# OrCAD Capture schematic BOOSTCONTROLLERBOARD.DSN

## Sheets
1 1 Microcontroller: size C; title: Boost Controller Board - Microcontroller; note: 10021168
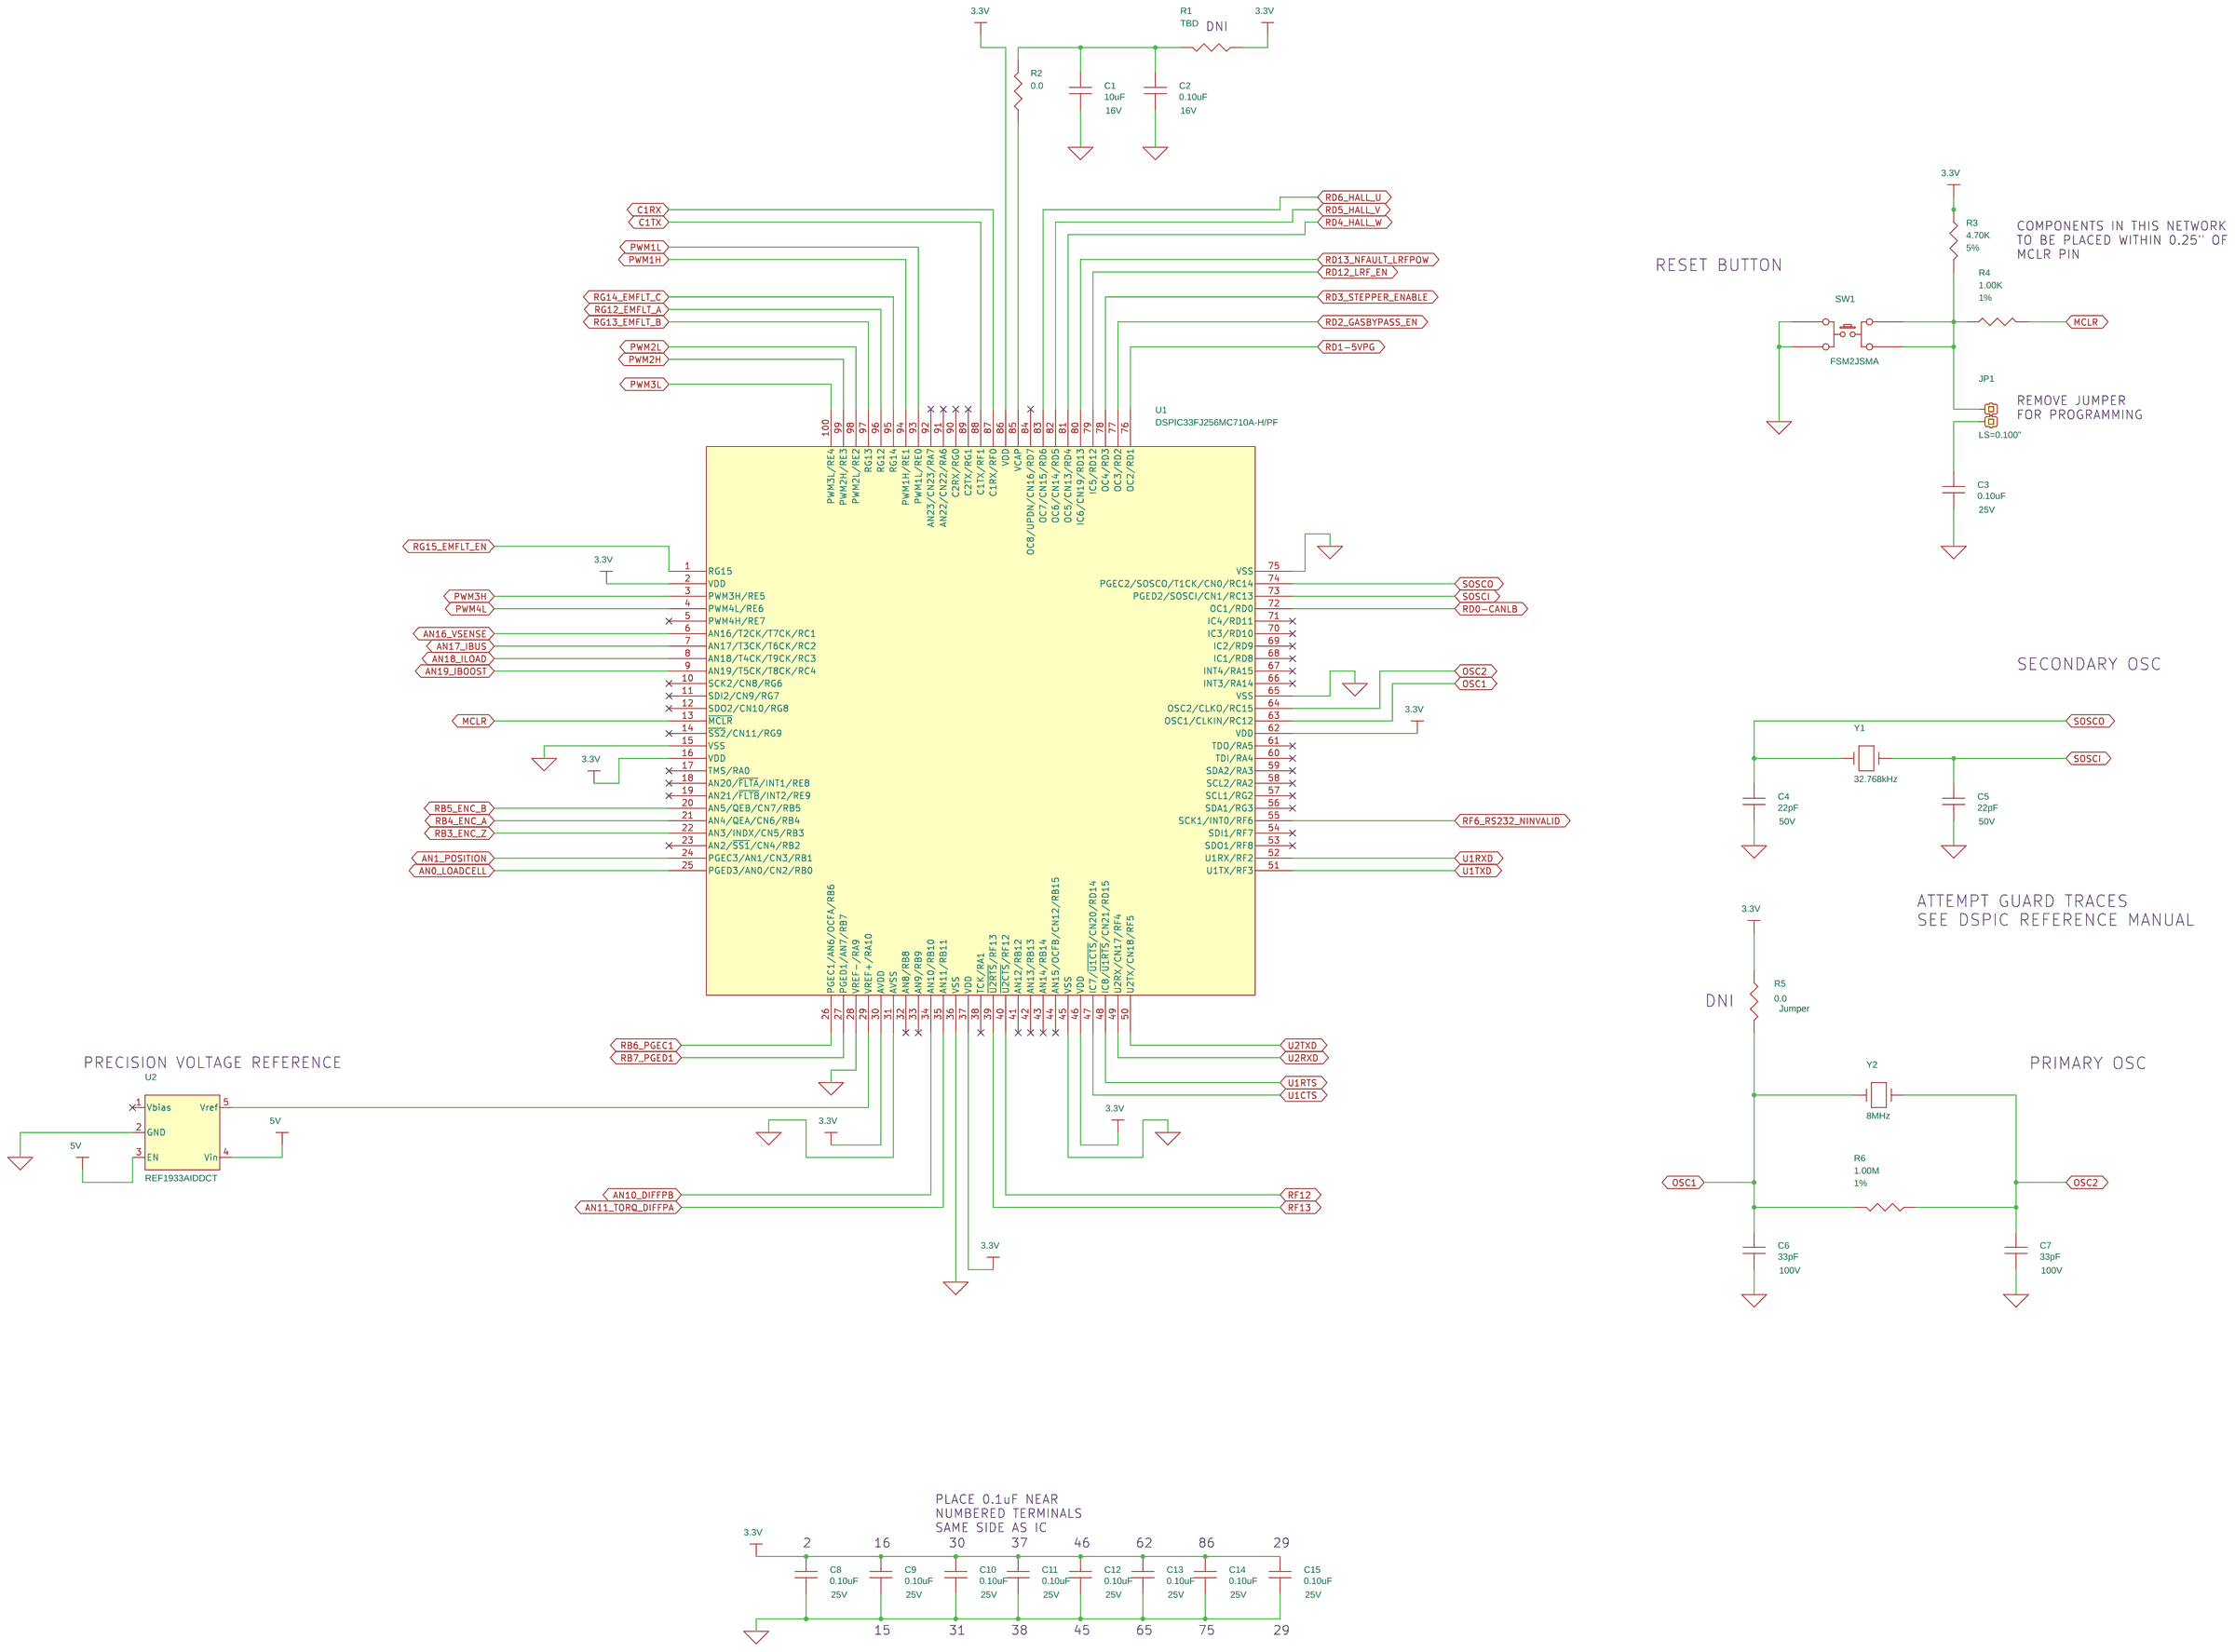
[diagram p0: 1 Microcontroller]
2 2 Power Supply: size C; title: Boost Controller Board - Power Supply
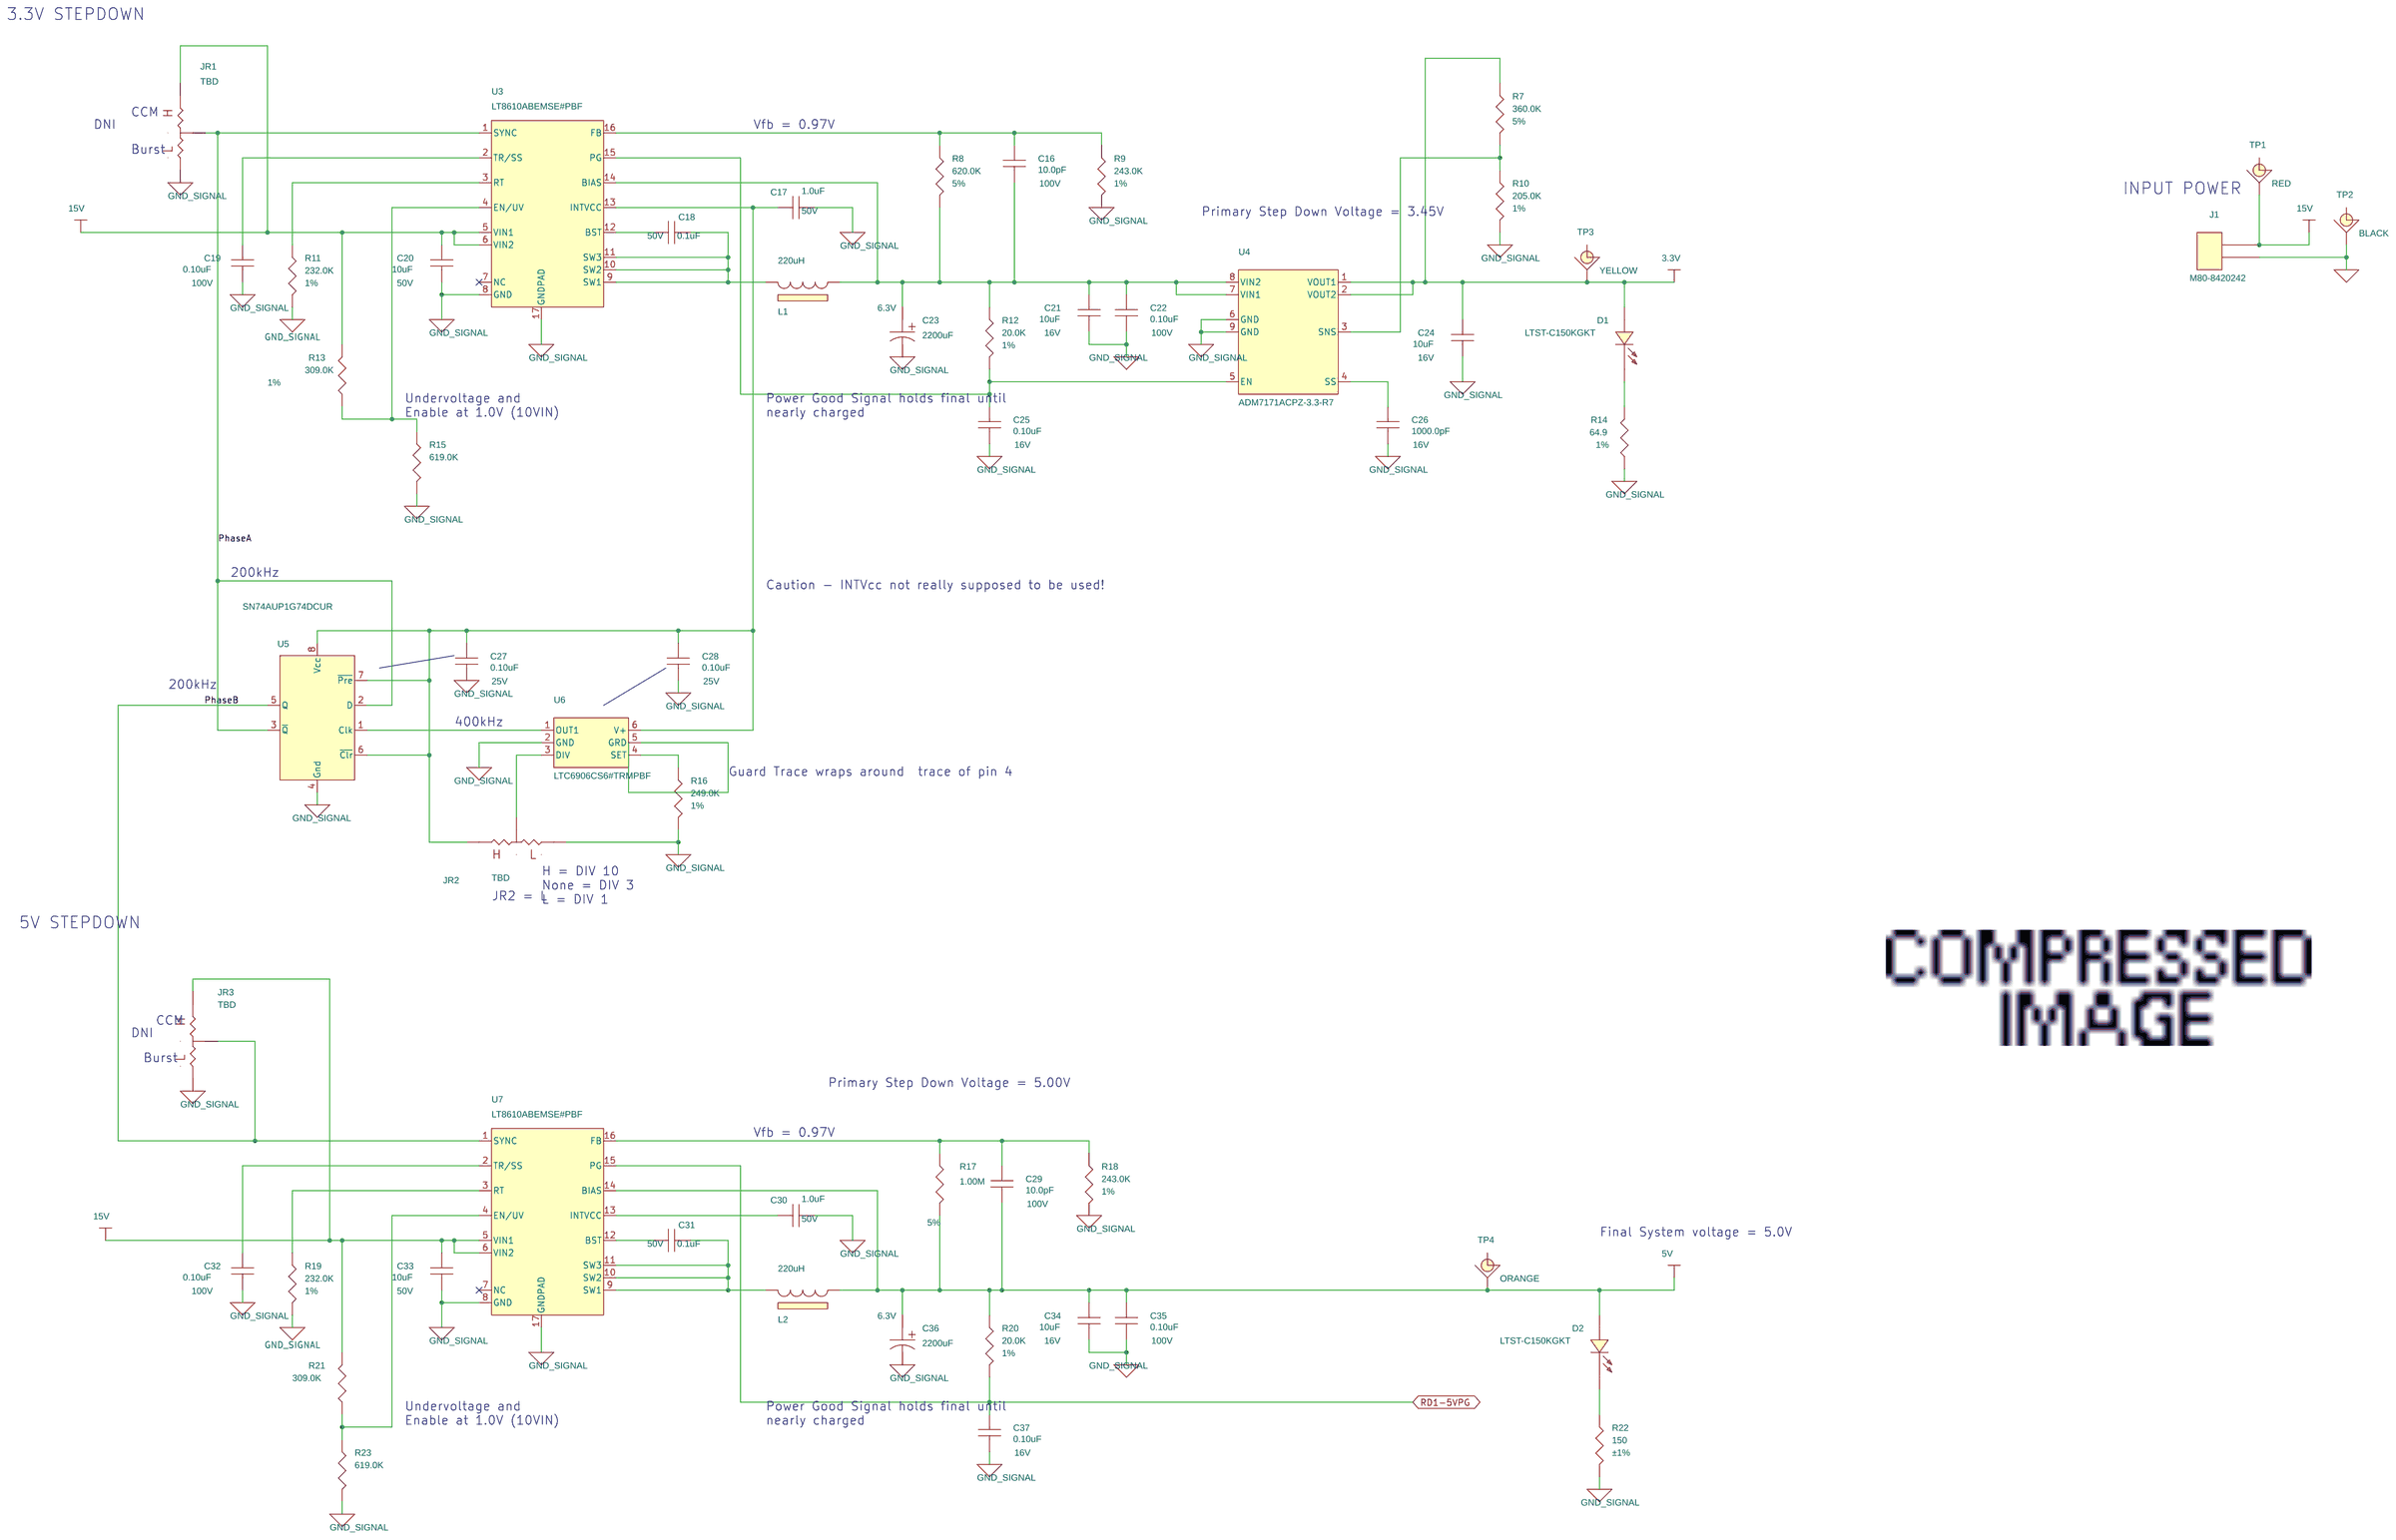
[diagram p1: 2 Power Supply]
3 3 Telemetry: size C; title: Boost Controller Board - Telemetry
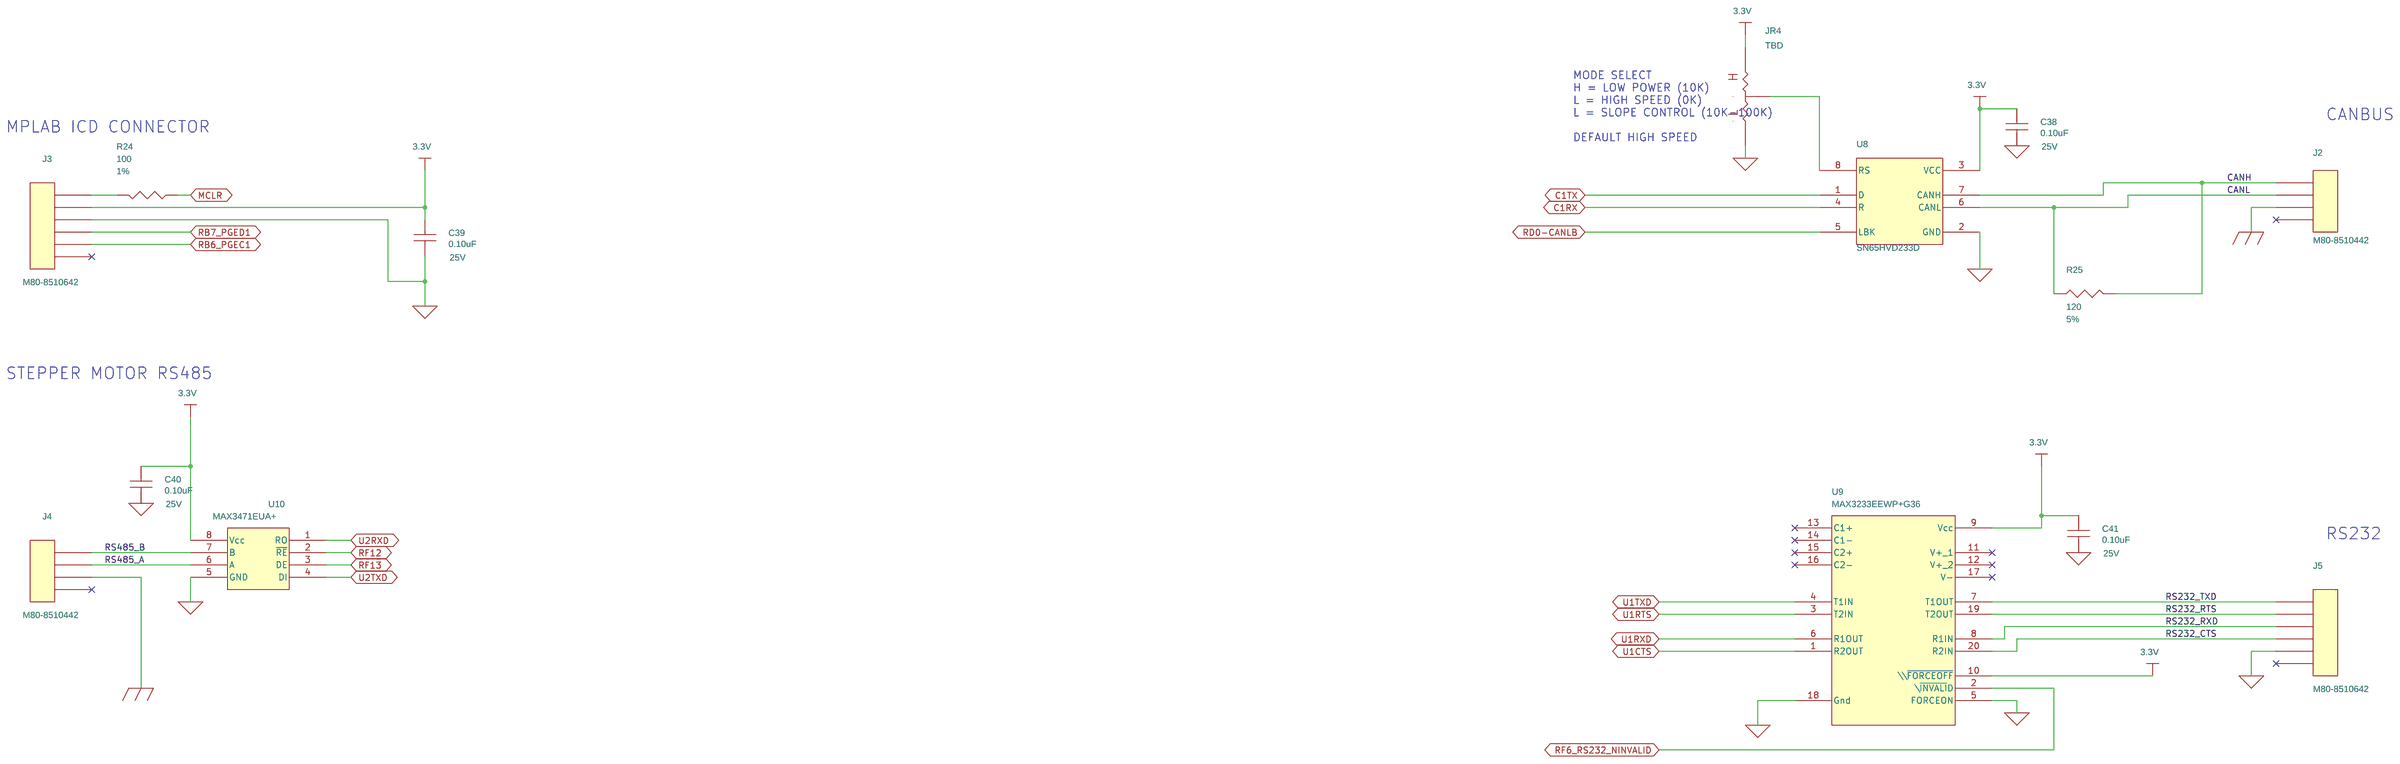
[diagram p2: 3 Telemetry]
4 5 Analog Inputs Sensors: size C; title: Boost Controller Board - Analog Inputs - Sensors
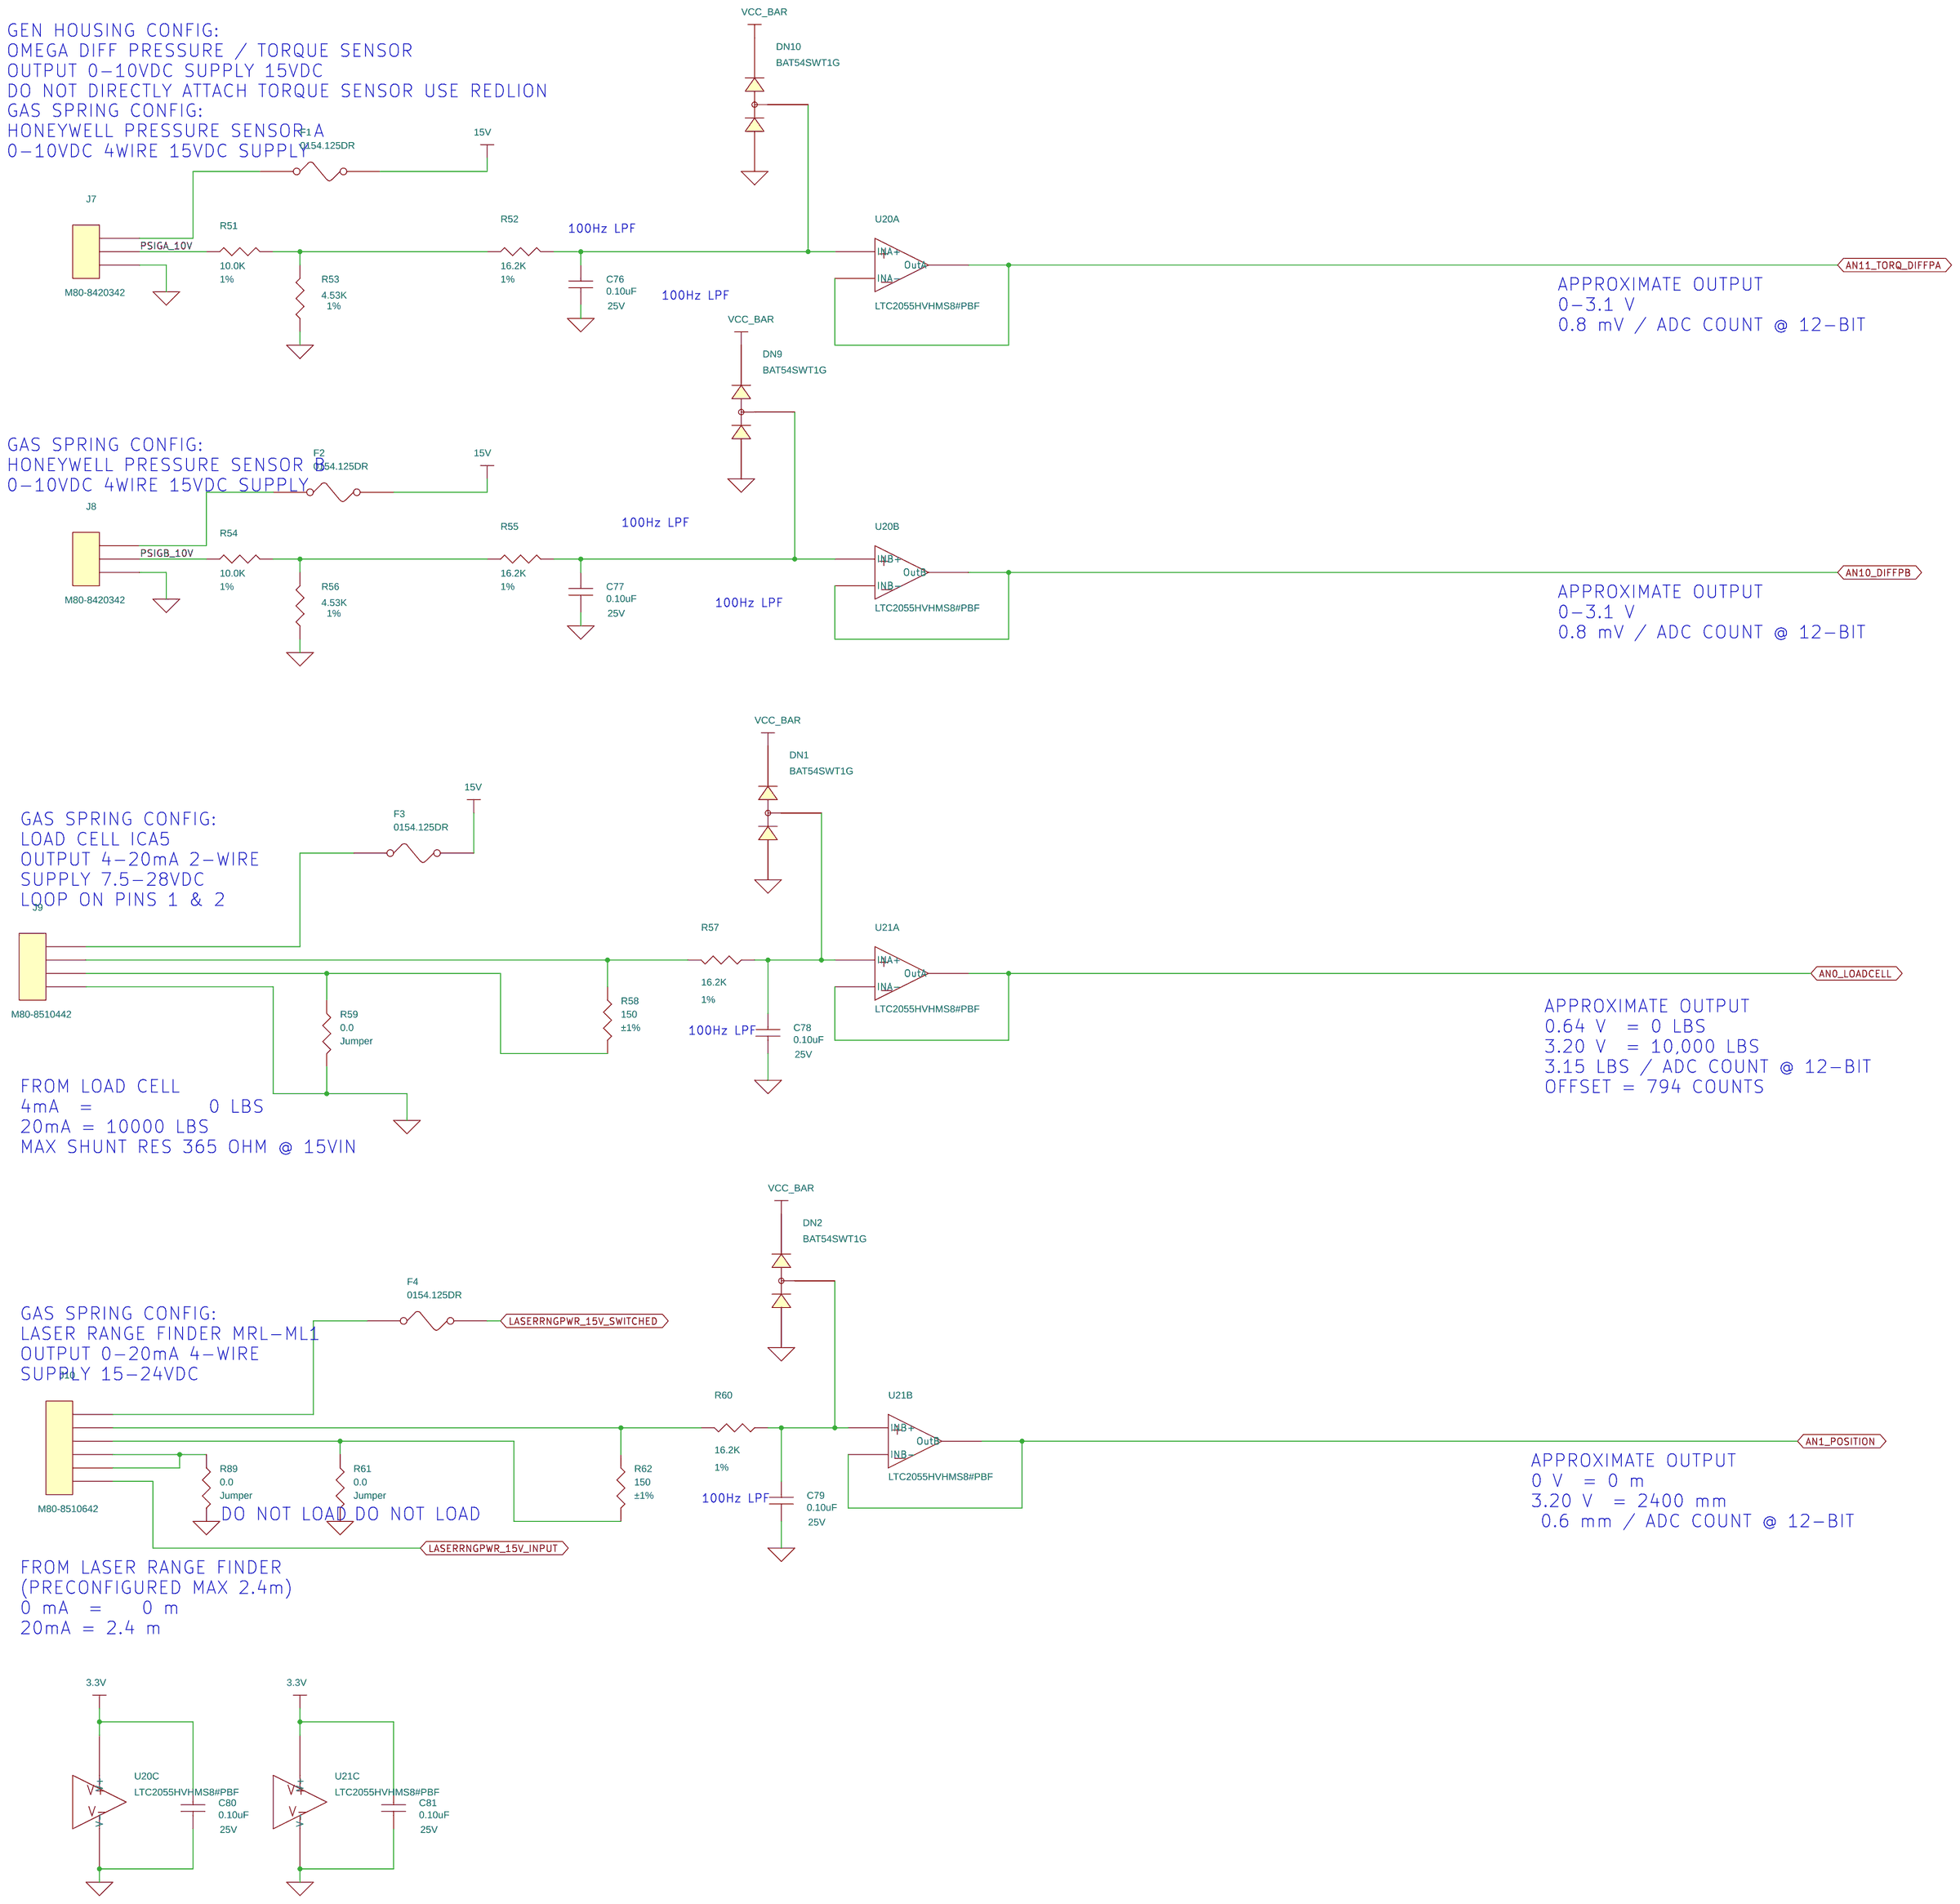
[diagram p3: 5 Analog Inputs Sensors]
5 6 Digital I/O: size C; title: Boost Controller Board - Digital I/O
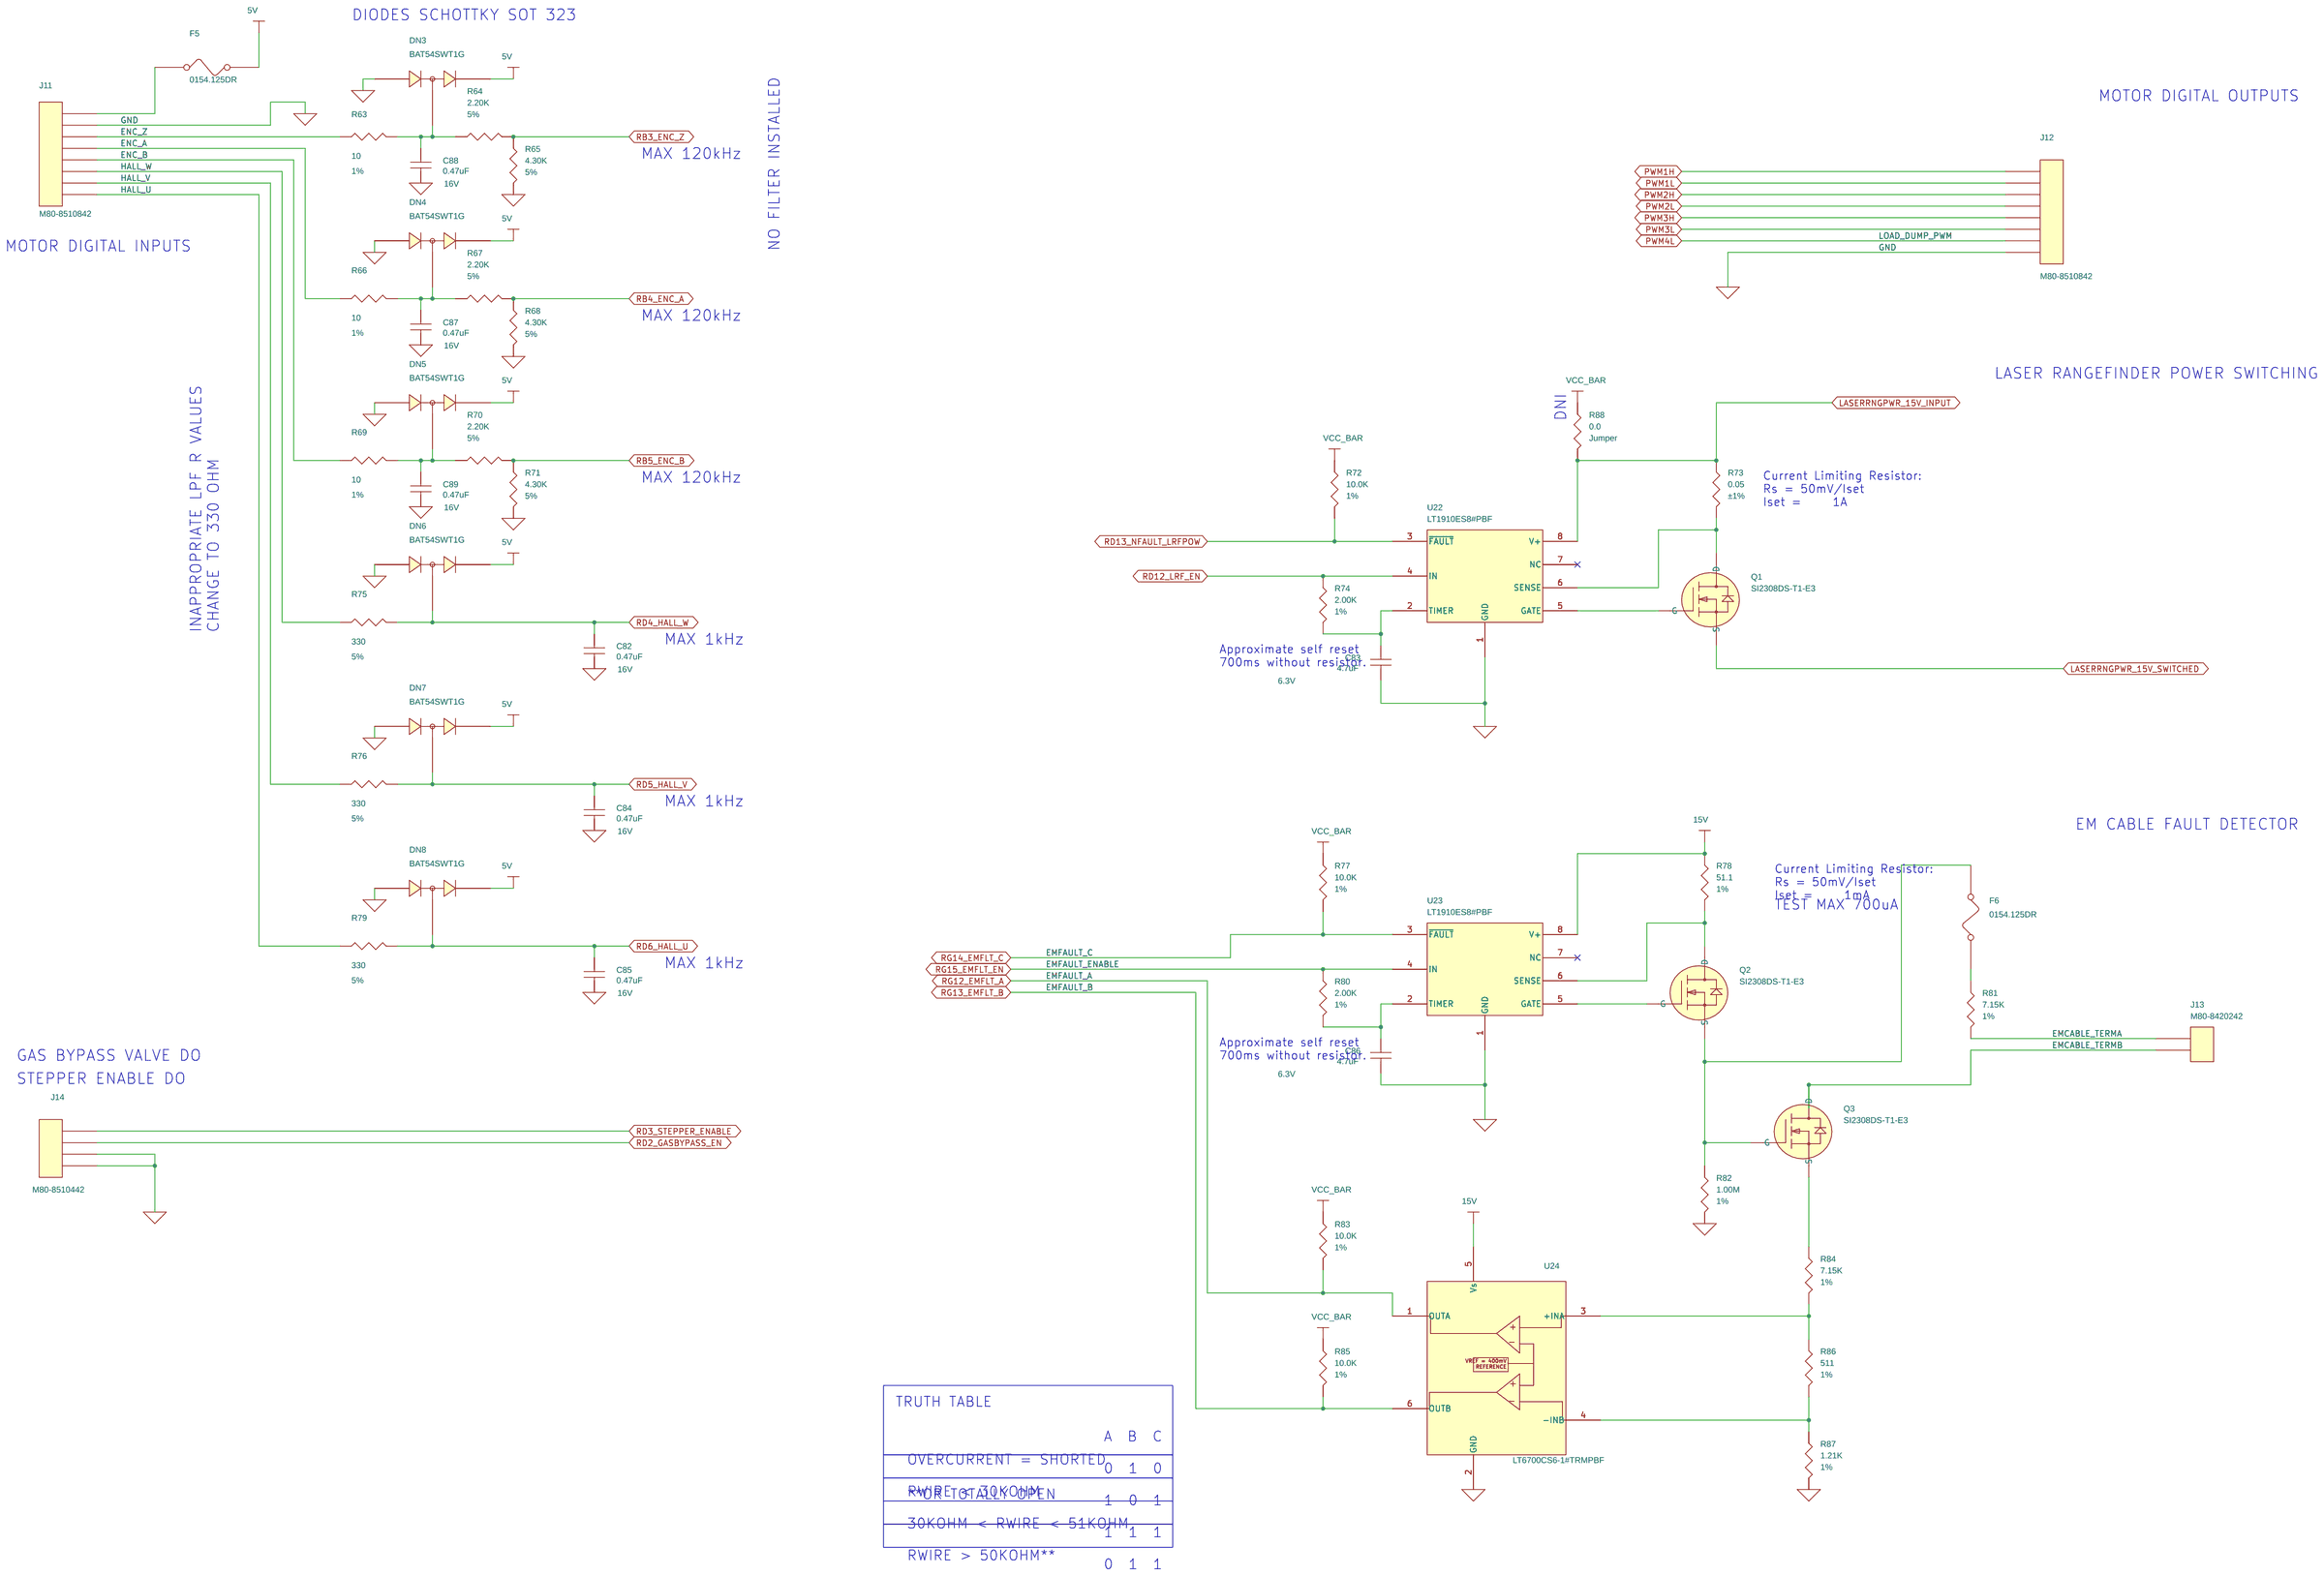
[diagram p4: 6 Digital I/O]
6 4 Analog Inputs V/I Monitors: size C; title: Boost Controller Board - Analog Inputs - Monitors
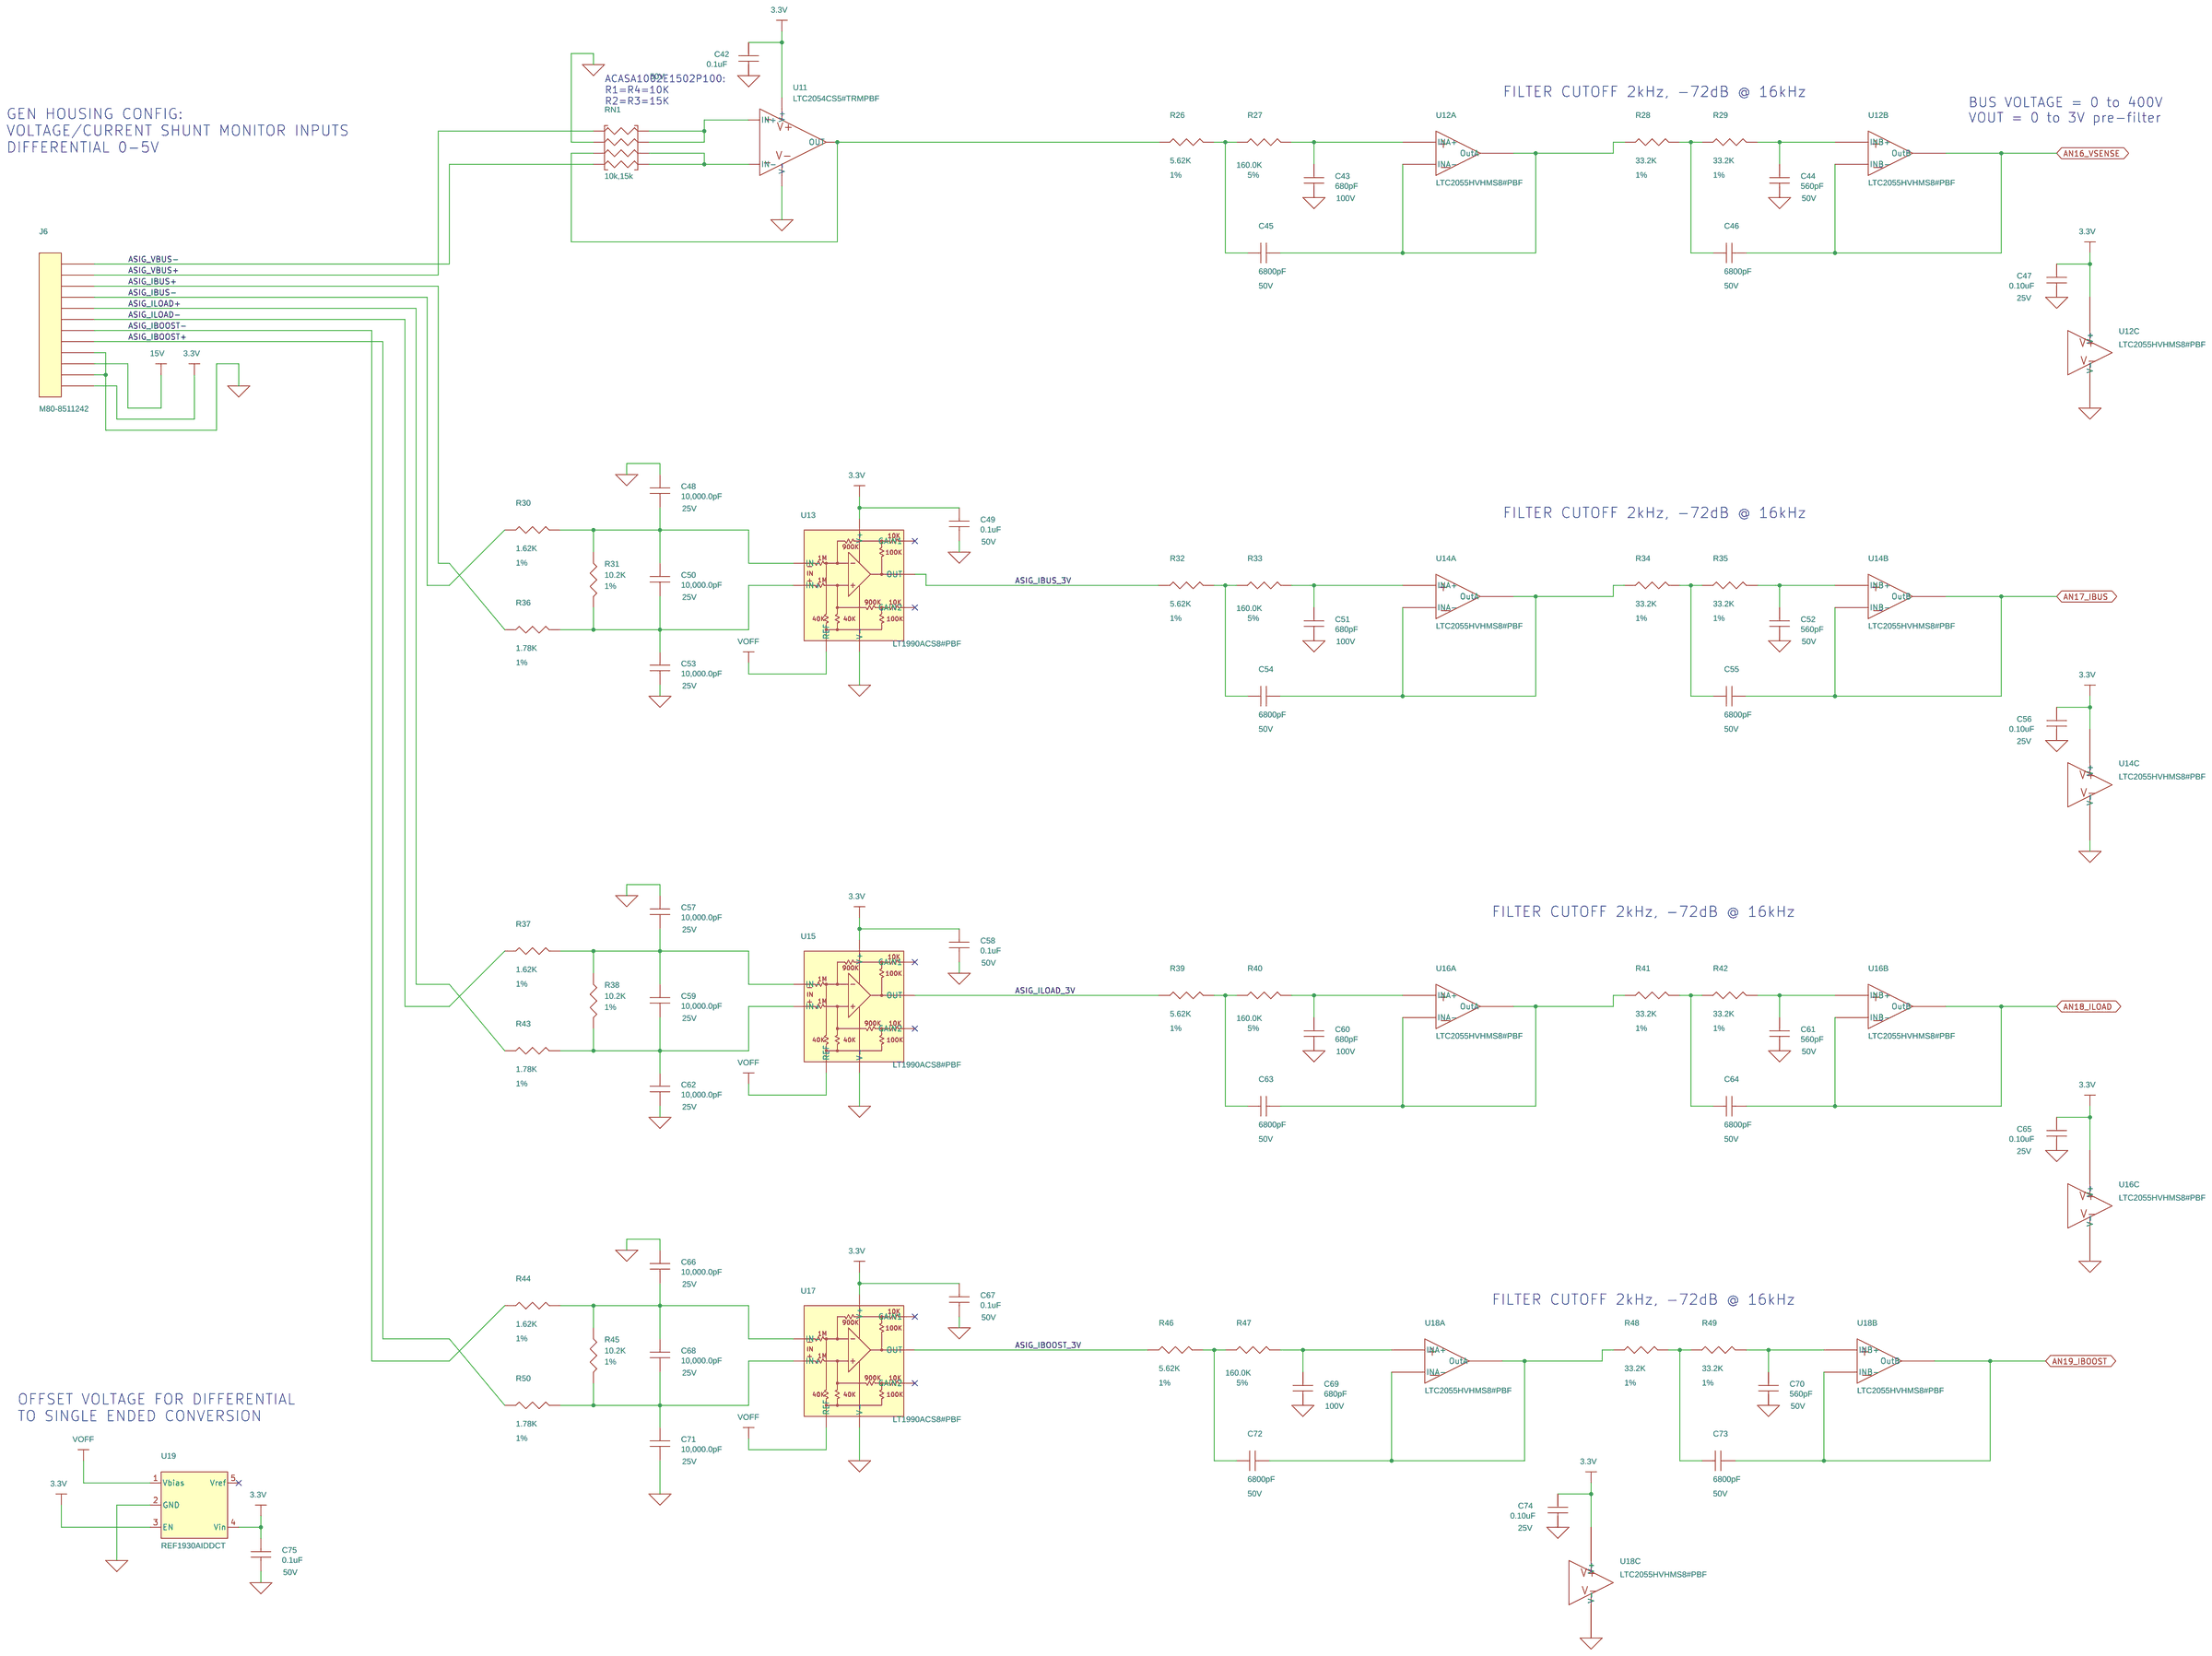
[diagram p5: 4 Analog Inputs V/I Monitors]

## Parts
sheet 1 Microcontroller
C1  10uF  [CAPC2012X135N]
C2  0.10uF  [CAPC1608X87N]
C3  0.10uF  [CAPC1608X87N]
C4  22pF  [CAPC1608X90N_G100]
C5  22pF  [CAPC1608X90N_G100]
C6  33pF  [CAPC1608X90N]
C7  33pF  [CAPC1608X90N]
C8  0.10uF  [CAPC1608X87N]
C9  0.10uF  [CAPC1608X87N]
C10  0.10uF  [CAPC1608X87N]
C11  0.10uF  [CAPC1608X87N]
C12  0.10uF  [CAPC1608X87N]
C13  0.10uF  [CAPC1608X87N]
C14  0.10uF  [CAPC1608X87N]
C15  0.10uF  [CAPC1608X87N]
JP1  LS=0.100"  [HDRV2W64P254_2X1_508X254H1363B]
R1  TBD  [RESC2012X50N]
R2  0.0  [RESC2012X50N]
R3  4.70K  [RESC1608X50N]
R4  1.00K  [RESC1608X50N]
R5  0.0  [RESC1609X55N]
R6  1.00M  [RESC2012X50N]
SW1  FSM2JSMA  [SOIC450P1000X459R-4N]
U1  DSPIC33FJ256MC710A-H/PF  [QFP50P1600X1600X120-100L30N]
U2  REF1933AIDDCT  [SOT95P280X110-5L30N]
Y1  32.768kHz  [OSCCC150X320X90-2N]
Y2  8MHz  [XTALSC500X500X135-2N]
sheet 2 Power Supply
C16  10.0pF  [CAPC2012X88N]
C17  1.0uF  [CAPC2012X140N]
C18  0.1uF  [CAPC2013X94N]
C19  0.10uF  [CAPC2012X110N]
C20  10uF  [CAPC5750X250N]
C21  10uF  [CAPC2012X135N]
C22  0.10uF  [CAPC2012X110N]
C23  2200uF  [CAPAE1030X1380DD450L320N]
C24  10uF  [CAPC2012X135N]
C25  0.10uF  [CAPC2012X100N]
C26  1000.0pF  [CAPC2012X88N]
C27  0.10uF  [CAPC1608X87N]
C28  0.10uF  [CAPC1608X87N]
C29  10.0pF  [CAPC2012X88N]
C30  1.0uF  [CAPC2012X140N]
C31  0.1uF  [CAPC2013X94N]
C32  0.10uF  [CAPC2012X110N]
C33  10uF  [CAPC5750X250N]
C34  10uF  [CAPC2012X135N]
C35  0.10uF  [CAPC2012X110N]
C36  2200uF  [CAPAE1030X1380DD450L320N]
C37  0.10uF  [CAPC2012X100N]
D1  LTST-C150KGKT  [LED_LTST-C150xxx]
D2  LTST-C150KGKT  [LED_LTST-C150xxx]
J1  M80-8420242  [HARWIN_M80-8420242]
JR1  TBD  [MISC_0805-3P-JMPR]
JR2  TBD  [MISC_0805-3P-JMPR]
JR3  TBD  [MISC_0805-3P-JMPR]
L1  220uH  [IND_NS-12]
L2  220uH  [IND_NS-12]
R7  360.0K  [RESC1608X50N]
R8  620.0K  [RESC2012X50N]
R9  243.0K  [RESC2012X50N]
R10  205.0K  [RESC1608X50N]
R11  232.0K  [RESC2012X50N]
R12  20.0K  [RESC2012X50N]
R13  309.0K  [RESC2012X50N]
R14  64.9  [RESC1608X50N]
R15  619.0K  [RESC2012X50N]
R16  249.0K  [RESC2012X50N]
R17  1.00M  [RESC1608X50N]
R18  243.0K  [RESC1608X50N]
R19  232.0K  [RESC2012X50N]
R20  20.0K  [RESC2012X50N]
R21  309.0K  [RESC2012X50N]
R22  150  [RESC1609X55N]
R23  619.0K  [RESC2012X50N]
TP1  RED  [TP_KEYSTONE_5000s_MINI]
TP2  BLACK  [TP_KEYSTONE_5000s_MINI]
TP3  YELLOW  [TP_KEYSTONE_5000s_MINI]
TP4  ORANGE  [TP_KEYSTONE_5000s_MINI]
U3  LT8610ABEMSE#PBF  [SOP50P490X110-17L30T175X364N]
U4  ADM7171ACPZ-3.3-R7  [SON50P300X300X80-9T170X254N]
U5  SN74AUP1G74DCUR  [SOP50P310X90-8N]
U6  LTC6906CS6#TRMPBF  [SOT95P280X100-6L20N]
U7  LT8610ABEMSE#PBF  [SOP50P490X110-17L30T175X364N]
sheet 3 Telemetry
C38  0.10uF  [CAPC1608X87N]
C39  0.10uF  [CAPC1608X87N]
C40  0.10uF  [CAPC1608X87N]
C41  0.10uF  [CAPC1608X87N]
J2  M80-8510442  [HARWIN_M80-8510442]
J3  M80-8510642  [HARWIN_M80-8510642]
J4  M80-8510442  [HARWIN_M80-8510442]
J5  M80-8510642  [HARWIN_M80-8510642]
JR4  TBD  [MISC_0805-3P-JMPR]
R24  100  [RESC2012X50N]
R25  120  [RESC2012X50N]
U8  SN65HVD233D  [SOIC127P600X175-8L87N]
U9  MAX3233EEWP+G36  [SOIC127P1032X265-20N]
U10  MAX3471EUA+  [SOP65P490X110-8L25N]
sheet 4 Analog Inputs V/I Monitors
C42  0.1uF  [CAPC2013X94N]
C43  680pF  [CAPC2012X88N]
C44  560pF  [CAPC1608X90N]
C45  6800pF  [CAPC2012X90N]
C46  6800pF  [CAPC2012X90N]
C47  0.10uF  [CAPC1608X87N]
C48  10,000.0pF  [CAPC2012X88N]
C49  0.1uF  [CAPC2013X94N]
C50  10,000.0pF  [CAPC2012X88N]
C51  680pF  [CAPC2012X88N]
C52  560pF  [CAPC1608X90N]
C53  10,000.0pF  [CAPC2012X88N]
C54  6800pF  [CAPC2012X90N]
C55  6800pF  [CAPC2012X90N]
C56  0.10uF  [CAPC1608X87N]
C57  10,000.0pF  [CAPC2012X88N]
C58  0.1uF  [CAPC2013X94N]
C59  10,000.0pF  [CAPC2012X88N]
C60  680pF  [CAPC2012X88N]
C61  560pF  [CAPC1608X90N]
C62  10,000.0pF  [CAPC2012X88N]
C63  6800pF  [CAPC2012X90N]
C64  6800pF  [CAPC2012X90N]
C65  0.10uF  [CAPC1608X87N]
C66  10,000.0pF  [CAPC2012X88N]
C67  0.1uF  [CAPC2013X94N]
C68  10,000.0pF  [CAPC2012X88N]
C69  680pF  [CAPC2012X88N]
C70  560pF  [CAPC1608X90N]
C71  10,000.0pF  [CAPC2012X88N]
C72  6800pF  [CAPC2012X90N]
C73  6800pF  [CAPC2012X90N]
C74  0.10uF  [CAPC1608X87N]
C75  0.1uF  [CAPC2013X94N]
J6  M80-8511242  [HARWIN_M80-8511242]
R26  5.62K  [RESC2012X50N]
R27  160.0K  [RESC2012X50N]
R28  33.2K  [RESC2012X50N]
R29  33.2K  [RESC2012X50N]
R30  1.62K  [RESC2012X50N]
R31  10.2K  [RESC2012X50N]
R32  5.62K  [RESC2012X50N]
R33  160.0K  [RESC2012X50N]
R34  33.2K  [RESC2012X50N]
R35  33.2K  [RESC2012X50N]
R36  1.78K  [RESC2012X50N]
R37  1.62K  [RESC2012X50N]
R38  10.2K  [RESC2012X50N]
R39  5.62K  [RESC2012X50N]
R40  160.0K  [RESC2012X50N]
R41  33.2K  [RESC2012X50N]
R42  33.2K  [RESC2012X50N]
R43  1.78K  [RESC2012X50N]
R44  1.62K  [RESC2012X50N]
R45  10.2K  [RESC2012X50N]
R46  5.62K  [RESC2012X50N]
R47  160.0K  [RESC2012X50N]
R48  33.2K  [RESC2012X50N]
R49  33.2K  [RESC2012X50N]
R50  1.78K  [RESC2012X50N]
RN1  10k,15k  [RESCAXS80P150X150X55-8N]
U11  LTC2054CS5#TRMPBF  [SOT95P280X100-5N]
U12  LTC2055HVHMS8#PBF  [SOP65P490X110-8L30N]  (sections A,B,C)
U13  LT1990ACS8#PBF  [SOIC127P599X175-8L86N]
U14  LTC2055HVHMS8#PBF  [SOP65P490X110-8L30N]  (sections A,B,C)
U15  LT1990ACS8#PBF  [SOIC127P599X175-8L86N]
U16  LTC2055HVHMS8#PBF  [SOP65P490X110-8L30N]  (sections A,B,C)
U17  LT1990ACS8#PBF  [SOIC127P599X175-8L86N]
U18  LTC2055HVHMS8#PBF  [SOP65P490X110-8L30N]  (sections A,B,C)
U19  REF1930AIDDCT  [SOT95P280X110-5L30N]
sheet 5 Analog Inputs Sensors
C76  0.10uF  [CAPC1608X87N]
C77  0.10uF  [CAPC1608X87N]
C78  0.10uF  [CAPC1608X87N]
C79  0.10uF  [CAPC1608X87N]
C80  0.10uF  [CAPC1608X87N]
C81  0.10uF  [CAPC1608X87N]
DN1  BAT54SWT1G  [SOT65P220X100-3N_132]
DN2  BAT54SWT1G  [SOT65P220X100-3N_132]
DN9  BAT54SWT1G  [SOT65P220X100-3N_132]
DN10  BAT54SWT1G  [SOT65P220X100-3N_132]
F1  0154.125DR  [FUSM9750X381N]
F2  0154.125DR  [FUSM9750X381N]
F3  0154.125DR  [FUSM9750X381N]
F4  0154.125DR  [FUSM9750X381N]
J7  M80-8420342  [HARWIN_M80-8420342]
J8  M80-8420342  [HARWIN_M80-8420342]
J9  M80-8510442  [HARWIN_M80-8510442]
J10  M80-8510642  [HARWIN_M80-8510642]
R51  10.0K  [RESC1608X50N]
R52  16.2K  [RESC1608X50N]
R53  4.53K  [RESC1608X50N]
R54  10.0K  [RESC1608X50N]
R55  16.2K  [RESC1608X50N]
R56  4.53K  [RESC1608X50N]
R57  16.2K  [RESC1608X50N]
R58  150  [RESC6332X70N]
R59  0.0  [RESC2012X50N]
R60  16.2K  [RESC1608X50N]
R61  0.0  [RESC2012X50N]
R62  150  [RESC6332X70N]
R89  0.0  [RESC2012X50N]
U20  LTC2055HVHMS8#PBF  [SOP65P490X110-8L30N]  (sections A,B,C)
U21  LTC2055HVHMS8#PBF  [SOP65P490X110-8L30N]  (sections A,B,C)
sheet 6 Digital I/O
C82  0.47uF  [CAPC1608X87N]
C83  4.7uF  [CAPC2012X140N]
C84  0.47uF  [CAPC1608X87N]
C85  0.47uF  [CAPC1608X87N]
C86  4.7uF  [CAPC2012X140N]
C87  0.47uF  [CAPC1608X87N]
C88  0.47uF  [CAPC1608X87N]
C89  0.47uF  [CAPC1608X87N]
DN3  BAT54SWT1G  [SOT65P220X100-3N_132]
DN4  BAT54SWT1G  [SOT65P220X100-3N_132]
DN5  BAT54SWT1G  [SOT65P220X100-3N_132]
DN6  BAT54SWT1G  [SOT65P220X100-3N_132]
DN7  BAT54SWT1G  [SOT65P220X100-3N_132]
DN8  BAT54SWT1G  [SOT65P220X100-3N_132]
F5  0154.125DR  [FUSM9750X381N]
F6  0154.125DR  [FUSM9750X381N]
J11  M80-8510842  [HARWIN_M80-8510842]
J12  M80-8510842  [HARWIN_M80-8510842]
J13  M80-8420242  [HARWIN_M80-8420242]
J14  M80-8510442  [HARWIN_M80-8510442]
Q1  SI2308DS-T1-E3  [SOT95P237X112-3N_132]
Q2  SI2308DS-T1-E3  [SOT95P237X112-3N_132]
Q3  SI2308DS-T1-E3  [SOT95P237X112-3N_132]
R63  10  [RESC1608X50N]
R64  2.20K  [RESC1608X50N]
R65  4.30K  [RESC1608X50N]
R66  10  [RESC1608X50N]
R67  2.20K  [RESC1608X50N]
R68  4.30K  [RESC1608X50N]
R69  10  [RESC1608X50N]
R70  2.20K  [RESC1608X50N]
R71  4.30K  [RESC1608X50N]
R72  10.0K  [RESC1608X50N]
R73  0.05  [RESC3116X65N]
R74  2.00K  [RESC1608X50N]
R75  330  [RESC1608X50N]
R76  330  [RESC1608X50N]
R77  10.0K  [RESC1608X50N]
R78  51.1  [RESC1608X50N]
R79  330  [RESC1608X50N]
R80  2.00K  [RESC1608X50N]
R81  7.15K  [RESC1608X50N]
R82  1.00M  [RESC1608X50N]
R83  10.0K  [RESC1608X50N]
R84  7.15K  [RESC1608X50N]
R85  10.0K  [RESC1608X50N]
R86  511  [RESC1608X50N]
R87  1.21K  [RESC1608X50N]
R88  0.0  [RESC2012X50N]
U22  LT1910ES8#PBF  [SOIC127P599X175-8L86N]
U23  LT1910ES8#PBF  [SOIC127P599X175-8L86N]
U24  LT6700CS6-1#TRMPBF  [SOT95P280X100-6L20N]

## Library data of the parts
C1 C21 C24 C34 = CAP: CAP CER 10UF 16V 20% X7R 0805; CLASS: DISCRETE; Dielectric Type: Capacitors; Manufacturer: Taiyo Yuden; Manufacturer PN: EMK212BB7106MG-T; PART_NUMBER: EMK212BB7106MG-T; Package Size: 0805 (2012 Metric); Rated Voltage: 16V; Temperature Coefficient: X7R; Tolerance: ±20%
C2 = CAP: CAP, CER, 0.10uF, 16V, 10%, X7R, 0603; CLASS: DISCRETE; Dielectric Type: Ceramic; Manufacturer: Kemet; Manufacturer PN: C0603C104K4RAC; PART_NUMBER: C0603C104K4RAC; Package Size: 0603; Rated Voltage: 16V; Temperature Coefficient: X7R; Tolerance: 10%
C3 C8-C15 C27 C28 C38-C41 C47 C56 C65 C74 C76-C81 = CAP: CAP CER 0.1UF 25V 10% X7R 0603; CLASS: DISCRETE; Dielectric Type: Ceramic; Manufacturer: Kemet; Manufacturer PN: C0603C104K3RACTU; PART_NUMBER: C0603C104K3RAC; Package Size: 0603; Rated Voltage: 25V; Temperature Coefficient: X7R; Tolerance: 10%
C4 C5 = CAP: CAP CER 22PF 50V 5% NP0 0603; CLASS: DISCRETE; Dielectric Type: Capacitors; Manufacturer: Murata Electronics North America; Manufacturer PN: GRM1885C1H220JA01D; PART_NUMBER: GRM1885C1H220JA01D; Package Size: 0603 (1608 Metric); Rated Voltage: 50V; Temperature Coefficient: C0G, NP0; Tolerance: ±5%
C6 C7 = CAP: CAP CER 33PF 100V 1% NP0 0603; CLASS: DISCRETE; Dielectric Type: Capacitors; Manufacturer: AVX Corporation; Manufacturer PN: 06031A330FAT2A; PART_NUMBER: 06031A330FAT2A; Package Size: 0603 (1608 Metric); Rated Voltage: 100V; Temperature Coefficient: C0G, NP0; Tolerance: ±1%
JP1 = JUMPER_2PIN: MISC 2 PIN JUMPER 0.100" PITCH 0.025" SQ; CLASS: IO; PART_NUMBER: MISC_JMPR-TH-2PIN
R1 = RES: TO BE DETERMINED, HEIGHT 0.5mm; CLASS: DISCRETE; PART_NUMBER: TBD_R0805; Package Size: 0805
R2 R59 R61 R88 R89 = RES: RES 0.0 OHM 1/8W JUMP 0805 SMD; CLASS: DISCRETE; Manufacturer: Vishay Dale; Manufacturer PN: CRCW08050000Z0EA; PART_NUMBER: CRCW08050000Z0EA; Package Size: 0805 (2012 Metric); Rated Power: 0.125W, 1/8W; Tolerance: Jumper
R3 = RES: CLASS: DISCRETE; Manufacturer: Vishay; Manufacturer PN: CRCW06034K70JNEA; PART_NUMBER: CRCW06034K70JNEA; Package Size: 0603; Rated Power: 0.1W; Temperature Coefficient: 200ppm/K; Tolerance: 5%
R4 = RES: CLASS: DISCRETE; Manufacturer: Vishay; Manufacturer PN: CRCW06031K00FKEA; PART_NUMBER: CRCW06031K00FKEA; Package Size: 0603; Rated Power: 0.1W; Temperature Coefficient: 100ppm/K; Tolerance: 1%
R5 = RES: RES 0.0 OHM 1/10W 0603 SMD; CLASS: DISCRETE; Manufacturer: Panasonic - ECG; Manufacturer PN: ERJ-3GEY0R00V; PART_NUMBER: ERJ-3GEY0R00V; Package Size: 0603 (1608 Metric); Rated Power: 0.1W, 1/10W; Temperature Coefficient: -100/ +600ppm/°C; Tolerance: Jumper
R6 = RES: RES 1.00M OHM 1/8W 1% 0805 SMD; CLASS: DISCRETE; Manufacturer: Vishay Dale; Manufacturer PN: CRCW08051M00FKEA; PART_NUMBER: CRCW08051M00FKEA; Package Size: 0805; Rated Power: 0.125W; Temperature Coefficient: 100ppm/K; Tolerance: 1%
SW1 = SW_SPST_12_34: SWITCH TACTILE SPST-NO 0.05A 12V; CLASS: DISCRETE; Manufacturer: TE Connectivity; Package Size: 6.00mm x 6.00mm
U1 = dsPIC33F_100TQFP: IC DSC 16BIT 256KB FLASH 100TQFP; CLASS: IC; Manufacturer: Microchip Technology; PART_NUMBER: DSPIC33FJ256MC710A-H/PF-ND; Package Size: 100-TQFP; Supply Voltage: 3 V - 3.6 V
U2 = REF19xx: IC VREF SERIES 3.3V SOT5; CLASS: IC; Manufacturer: Texas Instruments; Package Size: SOT-23-5 Thin, TSOT-23-5
Y1 = CRYSTAL: CRYSTAL 32.7680KHZ 12.5PF SMD; CLASS: DISCRETE; Frequency Tolerance: ±20ppm; Manufacturer: Epson Toyocom Corporation; Manufacturer PN: FC-135 32.7680KA-A3; PART_NUMBER: FC-135 32.7680KA-A3; Package Size: 2-SMD
Y2 = CRYSTAL: CRYSTAL 8.0000MHZ 18PF SMD; CLASS: DISCRETE; Frequency Stability: 30ppm; Frequency Tolerance: 30ppm; Manufacturer: TXC CORPORATION; Manufacturer PN: 7A-8.000MAAJ-T; PART_NUMBER: 7A-8.000MAAJ-T; Package Size: 0.197" L x 0.126" W (5.00mm x 3.20mm)
C16 C29 = CAP: CLASS: DISCRETE; Dielectric Type: Ceramic; Manufacturer: Kemet; Manufacturer PN: C0805C100J1GAC; PART_NUMBER: C0805C100J1GAC; Package Size: 0805; Rated Voltage: 100V; Temperature Coefficient: C0G(NP0); Tolerance: 5%
C17 C30 = CAP: CAP CER 1UF 50V 10% X7R 0805; CLASS: DISCRETE; Dielectric Type: Capacitors; Manufacturer: Kemet; Manufacturer PN: C0805C105K5RACTU; PART_NUMBER: C0805C105K5RACTU; Package Size: 0805 (2012 Metric); Rated Voltage: 50V; Temperature Coefficient: X7R; Tolerance: ±10%
C18 C31 C42 C49 C58 C67 C75 = CAP: CAP CER 0.1UF 50V 5% X7R 0805; CLASS: DISCRETE; Dielectric Type: Capacitors; Manufacturer: AVX Corporation; Manufacturer PN: 08055C104JAT2A; PART_NUMBER: 08055C104JAT2A; Package Size: 0805 (2012 Metric); Rated Voltage: 50V; Temperature Coefficient: X7R; Tolerance: ±5%
C19 C22 C32 C35 = CAP: CAP CER 0.1UF 100V 10% X7R 0805; CLASS: DISCRETE; Dielectric Type: Ceramic; Manufacturer: Kemet; Manufacturer PN: C0805C104K1RACTU; PART_NUMBER: C0805C104K1RAC; Package Size: 0805; Rated Voltage: 100V; Temperature Coefficient: X7R; Tolerance: 10%
C20 C33 = CAP: CAP CER 10UF 50V X7R 20% 2220; CLASS: DISCRETE; Dielectric Type: Ceramic; Manufacturer: TDK Corporation; Manufacturer PN: C5750X7R1H106M; PART_NUMBER: C5750X7R1H106M; Package Size: 2220 (5750 Metric); Rated Voltage: 50V; Temperature Coefficient: X7R; Tolerance: ±20%
C23 C36 = CAP_P: CAP ALUM 2200UF 6.3V 20% SMD; CLASS: DISCRETE; Dielectric Type: Capacitors; Manufacturer: Nichicon; Manufacturer PN: UCL0J222MNL1GS; PART_NUMBER: UCL0J222MNL1GS; Package Size: Radial, Can - SMD; Rated Voltage: 6.3V; Tolerance: 20%
C25 C37 = CAP: CLASS: DISCRETE; Dielectric Type: Ceramic; Manufacturer: Kemet; Manufacturer PN: C0805C104K4RAC; PART_NUMBER: C0805C104K4RAC; Package Size: 0805; Rated Voltage: 16V; Temperature Coefficient: X7R; Tolerance: 10%
C26 = CAP: CLASS: DISCRETE; Dielectric Type: Ceramic; Manufacturer: Kemet; Manufacturer PN: C0805C102K4RAC; PART_NUMBER: C0805C102K4RAC; Package Size: 0805; Rated Voltage: 16V; Temperature Coefficient: X7R; Tolerance: 10%
D1 D2 = LED: LED GREEN CLEAR 1206 SMD; CLASS: DISCRETE; Manufacturer: Lite-On Inc; Package Size: 1206 (3216 Metric); Rated Voltage: 2V
J1 J13 = CON2: CONN HDR 2MM R/A W/LATCH 2POS; CLASS: IO; Manufacturer: Harwin Inc
JR1-JR4 = RES_3PIN-JMPR: 0805 3PIN JUMPER; CLASS: DISCRETE; PART_NUMBER: SM_0805-3P-JMPR; Package Size: 0805
L1 L2 = IND_FERRITE: FIXED IND 220UH 1.35A 245 MOHM; CLASS: DISCRETE; Manufacturer: Taiyo Yuden; Manufacturer PN: NS12575T221MN; PART_NUMBER: NS12575T221MN; Package Size: Nonstandard; Tolerance: 20%
R7 = RES: CLASS: DISCRETE; Manufacturer: Vishay; Manufacturer PN: CRCW0603360KJNEA; PART_NUMBER: CRCW0603360KJNEA; Package Size: 0603; Rated Power: 0.1W; Temperature Coefficient: 200ppm/K; Tolerance: 5%
R8 = RES: CLASS: DISCRETE; Manufacturer: Vishay; Manufacturer PN: CRCW0805620KJNEA; PART_NUMBER: CRCW0805620KJNEA; Package Size: 0805; Rated Power: 0.125W; Temperature Coefficient: 200ppm/K; Tolerance: 5%
R9 = RES: CLASS: DISCRETE; Manufacturer: Vishay; Manufacturer PN: CRCW0805243KFKEA; PART_NUMBER: CRCW0805243KFKEA; Package Size: 0805; Rated Power: 0.125W; Temperature Coefficient: 100ppm/K; Tolerance: 1%
R10 = RES: CLASS: DISCRETE; Manufacturer: Vishay; Manufacturer PN: CRCW0603205KFKEA; PART_NUMBER: CRCW0603205KFKEA; Package Size: 0603; Rated Power: 0.1W; Temperature Coefficient: 100ppm/K; Tolerance: 1%
R11 R19 = RES: CLASS: DISCRETE; Manufacturer: Vishay; Manufacturer PN: CRCW0805232KFKEA; PART_NUMBER: CRCW0805232KFKEA; Package Size: 0805; Rated Power: 0.125W; Temperature Coefficient: 100ppm/K; Tolerance: 1%
R12 R20 = RES: CLASS: DISCRETE; Manufacturer: Vishay; Manufacturer PN: CRCW080520K0FKEA; PART_NUMBER: CRCW080520K0FKEA; Package Size: 0805; Rated Power: 0.125W; Temperature Coefficient: 100ppm/K; Tolerance: 1%
R13 R21 = RES: CLASS: DISCRETE; Manufacturer: Vishay; Manufacturer PN: CRCW0805309KFKEA; PART_NUMBER: CRCW0805309KFKEA; Package Size: 0805; Rated Power: 0.125W; Temperature Coefficient: 100ppm/K; Tolerance: 1%
R14 = RES: CLASS: DISCRETE; Manufacturer: Vishay; Manufacturer PN: CRCW060364R9FKEA; PART_NUMBER: CRCW060364R9FKEA; Package Size: 0603; Rated Power: 0.1W; Temperature Coefficient: 100ppm/K; Tolerance: 1%
R15 R23 = RES: CLASS: DISCRETE; Manufacturer: Vishay; Manufacturer PN: CRCW0805619KFKEA; PART_NUMBER: CRCW0805619KFKEA; Package Size: 0805; Rated Power: 0.125W; Temperature Coefficient: 100ppm/K; Tolerance: 1%
R16 = RES: RES 249K OHM 1/8W 1% 0805 SMD; CLASS: DISCRETE; Manufacturer: Vishay Dale; Manufacturer PN: CRCW0805249KFKEA; PART_NUMBER: CRCW0805249KFKEA; Package Size: 0805; Rated Power: 0.125W; Temperature Coefficient: 100ppm/K; Tolerance: 1%
R17 = RES: CLASS: DISCRETE; Manufacturer: Vishay; Manufacturer PN: CRCW06031M00JNEA; PART_NUMBER: CRCW06031M00JNEA; Package Size: 0603; Rated Power: 0.1W; Temperature Coefficient: 200ppm/K; Tolerance: 5%
R18 = RES: CLASS: DISCRETE; Manufacturer: Vishay; Manufacturer PN: CRCW0603243KFKEA; PART_NUMBER: CRCW0603243KFKEA; Package Size: 0603; Rated Power: 0.1W; Temperature Coefficient: 100ppm/K; Tolerance: 1%
R22 = RES: RES 150 OHM 1/10W 1% 0603 SMD; CLASS: DISCRETE; Manufacturer: Panasonic - ECG; Manufacturer PN: ERJ-3EKF1500V; PART_NUMBER: ERJ-3EKF1500V; Package Size: 0603 (1608 Metric); Rated Power: 0.1W, 1/10W; Temperature Coefficient: ±100ppm/°C; Tolerance: ±1%
TP1 = TESTPOINT: TEST POINT PC MINI .040"D RED; CLASS: DISCRETE; Manufacturer: Keystone Electronics; Manufacturer PN: 5000; PART_NUMBER: 5000; Package Size: 2.50 Dia
TP2 = TESTPOINT: TEST POINT PC MINI .040"D BLACK; CLASS: DISCRETE; Manufacturer: Keystone Electronics; Manufacturer PN: 5001; PART_NUMBER: 5001; Package Size: 2.50 Dia
TP3 = TESTPOINT: TEST POINT PC MINI .040"D YELLOW; CLASS: DISCRETE; Manufacturer: Keystone Electronics; Manufacturer PN: 5004; PART_NUMBER: 5004; Package Size: 2.50 Dia
TP4 = TESTPOINT: TEST POINT PC MINI .040"D ORANGE; CLASS: DISCRETE; Manufacturer: Keystone Electronics; Manufacturer PN: 5003; PART_NUMBER: 5003; Package Size: 2.50 Dia
U3 U7 = LT8610A: IC REG BUCK SYNC ADJ 3.5A 16MSOP; CLASS: IC; Manufacturer: Linear Technology; Package Size: 16-TFSOP (0.118", 3.00mm Width) Exposed Pad
U4 = ADM7171: IC REG LDO 3.3V 1A 8-LFCSP; CLASS: IC; Manufacturer: Analog Devices Inc; Package Size: 8-WFDFN Exposed Pad, CSP
U5 = 74xxx1G74DC-DLatch: IC POS-EDGE-TRIG D F-F-8-US8; CLASS: IC; Manufacturer: Texas Instruments; Package Size: 8-VFSOP (0.091", 2.30mm Width); Supply Voltage: 0.8 V ~ 3.6 V
U6 = LTC6906_S6: IC OSC SILICON PROG TSOT23-6; CLASS: IC; Manufacturer: Linear Technology; Package Size: SOT-23-6 Thin, TSOT-23-6; Supply Voltage: 2.25 V - 3.6 V
J2 J4 J9 J14 = CON4: CONN HDR 2MM R/A W/LATCH 4POS; CLASS: IO; Manufacturer: Harwin Inc
J3 J5 J10 = CON6: CONN HDR 2MM R/A W/LATCH 6POS; CLASS: IO; Manufacturer: Harwin Inc
R24 = RES: CLASS: DISCRETE; Manufacturer: Vishay; Manufacturer PN: CRCW0805100RFKEA; PART_NUMBER: CRCW0805100RFKEA; Package Size: 0805; Rated Power: 0.125W; Temperature Coefficient: 100ppm/K; Tolerance: 1%
R25 = RES: ES 120 OHM 1/8W 5% 0805 SMD; CLASS: DISCRETE; Manufacturer: Vishay; Manufacturer PN: CRCW0805120RJNEA; PART_NUMBER: CRCW0805120RJNEA; Package Size: 0805; Rated Power: 0.125W; Temperature Coefficient: 200ppm/K; Tolerance: 5%
U8 = SN65HVD233: IC 3.3V CAN TXRX 8-SOIC; CLASS: IC; Manufacturer: Texas Instruments; Package Size: 8-SOIC (0.154", 3.90mm Width); Supply Voltage: 3 V - 3.6 V
U9 = MAX3233E: IC TXRX RS232 DUAL250KBPS 20SOIC; CLASS: IC; Manufacturer: Maxim Integrated Products; PART_NUMBER: MAX3233EEWP_G36; Package Size: 20-SOIC (0.295", 7.50mm Width); Supply Voltage: 3 V ~ 3.6 V
U10 = MAX3471xUA: IC TXRX DIFF RS485/422 8-UMAX; CLASS: IC; Manufacturer: Maxim Integrated Products; Package Size: 8-TSSOP, 8-MSOP (0.118", 3.00mm Width); Supply Voltage: 2.5 V ~ 5.5 V
C43 C51 C60 C69 = CAP: CAP CER 680PF 100V 5% NP0 0805; CLASS: DISCRETE; Dielectric Type: Capacitors; Manufacturer: Kemet; Manufacturer PN: C0805C681J1GACTU; PART_NUMBER: C0805C681J1GACTU; Package Size: 0805 (2012 Metric); Rated Voltage: 100V; Temperature Coefficient: C0G, NP0; Tolerance: ±5%
C44 C52 C61 C70 = CAP: CAP CER 560PF 50V 10% X7R 0603; CLASS: DISCRETE; Dielectric Type: Capacitors; Manufacturer: Murata Electronics North America; Manufacturer PN: GRM188R71H561KA01D; PART_NUMBER: GRM188R71H561KA01D; Package Size: 0603 (1608 Metric); Rated Voltage: 50V; Temperature Coefficient: X7R; Tolerance: ±10%
C45 C46 C54 C55 C63 C64 C72 C73 = CAP: CAP CER 6800PF 50V 10% X7R 0805; CLASS: DISCRETE; Dielectric Type: Capacitors; Manufacturer: Yageo; Manufacturer PN: CC0805KRX7R9BB682; PART_NUMBER: CC0805KRX7R9BB682; Package Size: 0805 (2012 Metric); Rated Voltage: 50V; Temperature Coefficient: X7R; Tolerance: 10%
C48 C50 C53 C57 C59 C62 C66 C68 C71 = CAP: CAP CER 10000PF 25V X7R 0805; CLASS: DISCRETE; Dielectric Type: Ceramic; Manufacturer: Kemet; Manufacturer PN: C0805C103K3RAC; PART_NUMBER: C0805C103K3RAC; Package Size: 0805; Rated Voltage: 25V; Temperature Coefficient: X7R; Tolerance: 10%
J6 = CON12: CONN HDR 2MM R/A W/LATCH 12POS; CLASS: IO; Manufacturer: Harwin Inc
R26 R32 R39 R46 = RES: CLASS: DISCRETE; Manufacturer: Vishay; Manufacturer PN: CRCW08055K62FKEA; PART_NUMBER: CRCW08055K62FKEA; Package Size: 0805; Rated Power: 0.125W; Temperature Coefficient: 100ppm/K; Tolerance: 1%
R27 R33 R40 R47 = RES: CLASS: DISCRETE; Manufacturer: Vishay; Manufacturer PN: CRCW0805160KJNEA; PART_NUMBER: CRCW0805160KJNEA; Package Size: 0805; Rated Power: 0.125W; Temperature Coefficient: 200ppm/K; Tolerance: 5%
R28 R29 R34 R35 R41 R42 R48 R49 = RES: CLASS: DISCRETE; Manufacturer: Vishay; Manufacturer PN: CRCW080533K2FKEA; PART_NUMBER: CRCW080533K2FKEA; Package Size: 0805; Rated Power: 0.125W; Temperature Coefficient: 100ppm/K; Tolerance: 1%
R30 R37 R44 = RES: CLASS: DISCRETE; Manufacturer: Vishay; Manufacturer PN: CRCW08051K62FKEA; PART_NUMBER: CRCW08051K62FKEA; Package Size: 0805; Rated Power: 0.125W; Temperature Coefficient: 100ppm/K; Tolerance: 1%
R31 R38 R45 = RES: CLASS: DISCRETE; Manufacturer: Vishay; Manufacturer PN: CRCW080510K2FKEA; PART_NUMBER: CRCW080510K2FKEA; Package Size: 0805; Rated Power: 0.125W; Temperature Coefficient: 100ppm/K; Tolerance: 1%
R36 R43 R50 = RES: CLASS: DISCRETE; Manufacturer: Vishay; Manufacturer PN: CRCW08051K78FKEA; PART_NUMBER: CRCW08051K78FKEA; Package Size: 0805; Rated Power: 0.125W; Temperature Coefficient: 100ppm/K; Tolerance: 1%
RN1 = RES_ARRAY_4: RES ARRAY MULT OHM 4 RES 0612; CLASS: DISCRETE; Manufacturer: Vishay Beyschlag; Manufacturer PN: ACASA1002E1502P100; PART_NUMBER: ACASA1002E1502P100; Package Size: 1206 (3216 Metric), Convex, Long Side Terminals; Temperature Coefficient: 25ppm/C; Tolerance: 0.25%
U11 = LTC2054_S5: IC OPAMP SGL 0-DRIFT LP TSOT23-5; CLASS: IC; Manufacturer: Linear Technology; Package Size: SOT-23-5 Thin, TSOT-23-5; Supply Voltage: 2.7 V ~ 6 V
U12 U14 U16 U18 U20 U21 = LTC2055_MS8: IC OPAMP CHOPPER 500KHZ 8MSOP; CLASS: IC; Manufacturer: Linear Technology; Package Size: 8-TSSOP, 8-MSOP (0.118", 3.00mm Width); Supply Voltage: 2.7 V - 11 V, 1.35 V - 5.5 V
U13 U15 U17 = LT1990: IC OPAMP DIFF 105KHZ RRO 8SO; CLASS: IC; Manufacturer: Linear Technology; Package Size: 8-SOIC (0.154", 3.90mm Width); Supply Voltage: 2.7 V - 36 V, 1.35 V - 18 V
U19 = REF19xx: IC VREF SERIES 3V SOT5; CLASS: IC; Manufacturer: Texas Instruments; Package Size: SOT-23-5 Thin, TSOT-23-5
DN1-DN10 = DIODE_DUAL_ACJ: DIODE SCHOTTKY DUAL 30V SOT323; CLASS: DISCRETE; Manufacturer: ON Semiconductor; Package Size: SC-70, SOT-323; Rated Voltage: 800mV @ 100mA
F1-F6 = FUSEHOLDER_2T_2PIN: FUSEBLOCK W/.125A FUSE SMD FST; CLASS: DISCRETE; Manufacturer: Littelfuse Inc; Package Size: SMD w/Holder
J7 J8 = CON3: CONN HDR 2MM R/A W/LATCH 3POS; CLASS: IO; Manufacturer: Harwin Inc
R51 R54 R72 R77 R83 R85 = RES: CLASS: DISCRETE; Manufacturer: Vishay; Manufacturer PN: CRCW060310K0FKEA; PART_NUMBER: CRCW060310K0FKEA; Package Size: 0603; Rated Power: 0.1W; Temperature Coefficient: 100ppm/K; Tolerance: 1%
R52 R55 R57 R60 = RES: CLASS: DISCRETE; Manufacturer: Vishay; Manufacturer PN: CRCW060316K2FKEA; PART_NUMBER: CRCW060316K2FKEA; Package Size: 0603; Rated Power: 0.1W; Temperature Coefficient: 100ppm/K; Tolerance: 1%
R53 R56 = RES: CLASS: DISCRETE; Manufacturer: Vishay; Manufacturer PN: CRCW06034K53FKEA; PART_NUMBER: CRCW06034K53FKEA; Package Size: 0603; Rated Power: 0.1W; Temperature Coefficient: 100ppm/K; Tolerance: 1%
R58 R62 = RES: RES 150 OHM 1W 1% 2512 SMD; CLASS: DISCRETE; Manufacturer: Rohm Semiconductor; Manufacturer PN: MCR100JZHF1500; PART_NUMBER: MCR100JZHF1500; Package Size: 2512 (6432 Metric); Rated Power: 1W; Temperature Coefficient: ±100ppm/°C; Tolerance: ±1%
C82 C84 C85 C87-C89 = CAP: CLASS: DISCRETE; Dielectric Type: Ceramic; Manufacturer: Kemet; Manufacturer PN: C0603C474K4RAC; PART_NUMBER: C0603C474K4RAC; Package Size: 0603; Rated Voltage: 16V; Temperature Coefficient: X7R; Tolerance: 10%
C83 C86 = CAP: CAP CER 4.7UF 6.3V 10% X7R 0805; CLASS: DISCRETE; Dielectric Type: Capacitors; Manufacturer: Kemet; Manufacturer PN: C0805C475K9RACTU; PART_NUMBER: C0805C475K9RACTU; Package Size: 0805 (2012 Metric); Rated Voltage: 6.3V; Temperature Coefficient: X7R; Tolerance: 10%
J11 J12 = CON8: CONN HDR 2MM R/A W/LATCH 8POS; CLASS: IO; Manufacturer: Harwin Inc
Q1-Q3 = MOSFET_I_EN_GSD: MOSFET N-CH 60V 2A SOT23-3; CLASS: DISCRETE; Manufacturer: Vishay/Siliconix; Package Size: SOT-23-3, TO-236-3, Micro3™, SSD3, SST3; Rated Power: 1.25W
R63 R66 R69 = RES: CLASS: DISCRETE; Manufacturer: Vishay; Manufacturer PN: CRCW060310R0FKEA; PART_NUMBER: CRCW060310R0FKEA; Package Size: 0603; Rated Power: 0.1W; Temperature Coefficient: 100ppm/K; Tolerance: 1%
R64 R67 R70 = RES: CLASS: DISCRETE; Manufacturer: Vishay; Manufacturer PN: CRCW06032K20JNEA; PART_NUMBER: CRCW06032K20JNEA; Package Size: 0603; Rated Power: 0.1W; Temperature Coefficient: 200ppm/K; Tolerance: 5%
R65 R68 R71 = RES: CLASS: DISCRETE; Manufacturer: Vishay; Manufacturer PN: CRCW06034K30JNEA; PART_NUMBER: CRCW06034K30JNEA; Package Size: 0603; Rated Power: 0.1W; Temperature Coefficient: 200ppm/K; Tolerance: 5%
R73 = RES: RES .05 OHM 1/2W 1% 1206 SMD; CLASS: DISCRETE; Manufacturer: Stackpole Electronics Inc; Manufacturer PN: CSR1206FK50L0; PART_NUMBER: CSR1206FK50L0; Package Size: 1206 (3216 Metric); Rated Power: 0.5W, 1/2W; Temperature Coefficient: ±100ppm/°C; Tolerance: ±1%
R74 R80 = RES: CLASS: DISCRETE; Manufacturer: Vishay; Manufacturer PN: CRCW06032K00FKEA; PART_NUMBER: CRCW06032K00FKEA; Package Size: 0603; Rated Power: 0.1W; Temperature Coefficient: 100ppm/K; Tolerance: 1%
R75 R76 R79 = RES: CLASS: DISCRETE; Manufacturer: Vishay; Manufacturer PN: CRCW0603330RJNEA; PART_NUMBER: CRCW0603330RJNEA; Package Size: 0603; Rated Power: 0.1W; Temperature Coefficient: 200ppm/K; Tolerance: 5%
R78 = RES: CLASS: DISCRETE; Manufacturer: Vishay; Manufacturer PN: CRCW060351R1FKEA; PART_NUMBER: CRCW060351R1FKEA; Package Size: 0603; Rated Power: 0.1W; Temperature Coefficient: 100ppm/K; Tolerance: 1%
R81 R84 = RES: CLASS: DISCRETE; Manufacturer: Vishay; Manufacturer PN: CRCW06037K15FKEA; PART_NUMBER: CRCW06037K15FKEA; Package Size: 0603; Rated Power: 0.1W; Temperature Coefficient: 100ppm/K; Tolerance: 1%
R82 = RES: CLASS: DISCRETE; Manufacturer: Vishay; Manufacturer PN: CRCW06031M00FKEA; PART_NUMBER: CRCW06031M00FKEA; Package Size: 0603; Rated Power: 0.1W; Temperature Coefficient: 100ppm/K; Tolerance: 1%
R86 = RES: CLASS: DISCRETE; Manufacturer: Vishay; Manufacturer PN: CRCW0603511RFKEA; PART_NUMBER: CRCW0603511RFKEA; Package Size: 0603; Rated Power: 0.1W; Temperature Coefficient: 100ppm/K; Tolerance: 1%
R87 = RES: CLASS: DISCRETE; Manufacturer: Vishay; Manufacturer PN: CRCW06031K21FKEA; PART_NUMBER: CRCW06031K21FKEA; Package Size: 0603; Rated Power: 0.1W; Temperature Coefficient: 100ppm/K; Tolerance: 1%
U22 U23 = LT1910: IC MOSFET DRIVER HIGH-SIDE 8SOIC; CLASS: DISCRETE; Manufacturer: Linear Technology; Package Size: 8-SOIC (0.154", 3.90mm Width)
U24 = LT6700-1: IC COMP DUAL 400MV REF TSOT23-6; CLASS: IC; Manufacturer: Linear Technology; Package Size: SOT-23-6 Thin, TSOT-23-6; Supply Voltage: 1.4 V - 18 V

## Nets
3.3V: C8.1 C9.1 C10.1 C11.1 C12.1 C13.1 C14.1 C15.1 C24.1 C38.1 C39.1 C40.1 C41.1 C42.1 C47.1 C49.1 C56.1 C58.1 C65.1 C67.1 C74.1 C75.1 C80.1 C81.1 D1.A DN1.2(C) DN2.2(C) DN9.2(C) DN10.2(C) J3.2 J6.12 JR4.1 R1.1 R3.1 R5.1 R7.1 R72.1 R77.1 R83.1 R85.1 TP3.1(TP) U1.2(VDD) U1.16(VDD) U1.30(AVDD) U1.37(VDD) U1.46(VDD) U1.62(VDD) U1.86(VDD) U4.1(VOUT1) U4.2(VOUT2) U8.3(VCC) U9.9(Vcc) U9.10(\\~{FORCEOFF}) U10.8(Vcc) U11.5(V+) U12.8(V+) U13.7(V+) U14.8(V+) U15.7(V+) U16.8(V+) U17.7(V+) U18.8(V+) U19.3(EN) U19.4(Vin) U20.8(V+) U21.8(V+)
5V: C29.2 C34.1 C35.1 C36.1 D2.A DN3.2(C) DN4.2(C) DN5.2(C) DN6.2(C) DN7.2(C) DN8.2(C) F5.2 L2.2 R17.2 R20.1 TP4.1(TP) U2.3(EN) U2.4(Vin) U7.14(BIAS)
15V: C20.1 C33.1 F1.2 F2.2 F3.2 J1.1 J6.10 JR1.1 JR3.1 R13.1 R21.1 R78.1 R88.1 TP1.1(TP) U3.5(VIN1) U3.6(VIN2) U7.5(VIN1) U7.6(VIN2) U23.8(V+) U24.5(Vs)
GND_EARTH: J2.3 J4.3
GND_SIGNAL: C1.2 C2.2 C3.2 C4.2 C5.2 C6.2 C7.2 C8.2 C9.2 C10.2 C11.2 C12.2 C13.2 C14.2 C15.2 C17.2 C19.2 C20.2 C21.2 C22.2 C23.2 C24.2 C25.2 C26.2 C27.2 C28.2 C30.2 C32.2 C33.2 C34.2 C35.2 C36.2 C37.2 C38.2 C39.2 C40.2 C41.2 C42.2 C43.2 C44.2 C47.2 C48.1 C49.2 C51.2 C52.2 C53.2 C56.2 C57.1 C58.2 C60.2 C61.2 C62.2 C65.2 C66.1 C67.2 C69.2 C70.2 C71.2 C74.2 C75.2 C76.2 C77.2 C78.2 C79.2 C80.2 C81.2 C82.2 C83.2 C84.2 C85.2 C86.2 C87.2 C88.2 C89.2 DN1.1(A) DN2.1(A) DN3.1(A) DN4.1(A) DN5.1(A) DN6.1(A) DN7.1(A) DN8.1(A) DN9.1(A) DN10.1(A) J1.2 J3.3 J5.5 J6.9 J6.11 J7.3 J8.3 J9.4 J11.2 J12.8 J14.3 J14.4 JR1.3 JR2.3 JR3.3 JR4.3 R9.2 R10.2 R11.2 R14.2 R15.2 R16.2 R18.2 R19.2 R22.2 R23.2 R53.1 R56.1 R59.2 R61.2 R65.2 R68.2 R71.2 R82.2 R87.2 R89.2 RN1.2 SW1.1 SW1.2 TP2.1(TP) U1.15(VSS) U1.28(VREF-/RA9) U1.31(AVSS) U1.36(VSS) U1.45(VSS) U1.65(VSS) U1.75(VSS) U2.2(GND) U3.8(GND) U3.17(GNDPAD) U4.6(GND) U4.9(GND) U5.4(Gnd) U6.2(GND) U7.8(GND) U7.17(GNDPAD) U8.2(GND) U9.5(FORCEON) U9.18(Gnd) U10.5(GND) U11.2(V-) U12.4(V-) U13.4(V-) U14.4(V-) U15.4(V-) U16.4(V-) U17.4(V-) U18.4(V-) U19.2(GND) U20.4(V-) U21.4(V-) U22.1(GND) U23.1(GND) U24.2(GND)
AN0_LOADCELL: U1.25(PGED3/AN0/CN2/RB0) U21.1(OutA) U21.2(INA-)
AN1_POSITION: U1.24(PGEC3/AN1/CN3/RB1) U21.6(INB-) U21.7(OutB)
AN10_DIFFPB: U1.34(AN10/RB10) U20.6(INB-) U20.7(OutB)
AN11_TORQ_DIFFPA: U1.35(AN11/RB11) U20.1(OutA) U20.2(INA-)
AN16_VSENSE: C46.2 U1.6(AN16/T2CK/T7CK/RC1) U12.6(INB-) U12.7(OutB)
AN17_IBUS: C55.2 U1.7(AN17/T3CK/T6CK/RC2) U14.6(INB-) U14.7(OutB)
AN18_ILOAD: C64.2 U1.8(AN18/T4CK/T9CK/RC3) U16.6(INB-) U16.7(OutB)
AN19_IBOOST: C73.2 U1.9(AN19/T5CK/T8CK/RC4) U18.6(INB-) U18.7(OutB)
ASIG_IBOOST+: J6.8 R50.1
ASIG_IBOOST-: J6.7 R44.1
ASIG_IBOOST_3V: R46.1 U17.6(OUT)
ASIG_IBUS+: J6.3 R36.1
ASIG_IBUS-: J6.4 R30.1
ASIG_IBUS_3V: R32.1 U13.6(OUT)
ASIG_ILOAD+: J6.5 R43.1
ASIG_ILOAD-: J6.6 R37.1
ASIG_ILOAD_3V: R39.1 U15.6(OUT)
ASIG_VBUS+: J6.2 RN1.1
ASIG_VBUS-: J6.1 RN1.4
C1RX: U1.87(C1RX/RF0) U8.4(R)
C1TX: U1.88(C1TX/RF1) U8.1(D)
CANH: J2.1 R25.2 U8.7(CANH)
CANL: J2.2 R25.1 U8.6(CANL)
EMCABLE_TERMA: J13.1 R81.2
EMCABLE_TERMB: J13.2 Q3.3(D)
ENC_A: J11.4 R66.1
ENC_B: J11.5 R69.1
ENC_Z: J11.3 R63.1
HALL_U: J11.8 R79.1
HALL_V: J11.7 R76.1
HALL_W: J11.6 R75.1
LASERRNGPWR_15V_INPUT: J10.6 R73.1 R88.2 U22.8(V+)
LASERRNGPWR_15V_SWITCHED: F4.2 Q1.2(S)
MCLR: R4.2 R24.1 U1.13(~{MCLR})
OSC1: C6.1 R5.2 R6.2 U1.63(OSC1/CLKIN/RC12) Y2.1
OSC2: C7.1 R6.1 U1.64(OSC2/CLKO/RC15) Y2.2
PhaseA: JR1.2 U3.1(SYNC) U5.2(D) U5.3(~{Q})
PhaseB: JR3.2 U5.5(Q) U7.1(SYNC)
PSIGA_10V: J7.2 R51.1
PSIGB_10V: J8.2 R54.1
PWM1H: J12.1 U1.94(PWM1H/RE1)
PWM1L: J12.2 U1.93(PWM1L/RE0)
PWM2H: J12.3 U1.99(PWM2H/RE3)
PWM2L: J12.4 U1.98(PWM2L/RE2)
PWM3H: J12.5 U1.3(PWM3H/RE5)
PWM3L: J12.6 U1.100(PWM3L/RE4)
PWM4L: J12.7 U1.4(PWM4L/RE6)
RB3_ENC_Z: R64.2 R65.1 U1.22(AN3/INDX/CN5/RB3)
RB4_ENC_A: R67.2 R68.1 U1.21(AN4/QEA/CN6/RB4)
RB5_ENC_B: R70.2 R71.1 U1.20(AN5/QEB/CN7/RB5)
RB6_PGEC1: J3.5 U1.26(PGEC1/AN6/OCFA/RB6)
RB7_PGED1: J3.4 U1.27(PGED1/AN7/RB7)
RD0-CANLB: U1.72(OC1/RD0) U8.5(LBK)
RD1-5VPG: C37.1 R20.2 U1.76(OC2/RD1) U7.15(PG)
RD2_GASBYPASS_EN: J14.2 U1.77(OC3/RD2)
RD3_STEPPER_ENABLE: J14.1 U1.78(OC4/RD3)
RD4_HALL_W: C82.1 DN6.3(J) R75.2 U1.81(OC5/CN13/RD4)
RD5_HALL_V: C84.1 DN7.3(J) R76.2 U1.82(OC6/CN14/RD5)
RD6_HALL_U: C85.1 DN8.3(J) R79.2 U1.83(OC7/CN15/RD6)
RD12_LRF_EN: R74.1 U1.79(IC5/RD12) U22.4(IN)
RD13_NFAULT_LRFPOW: R72.2 U1.80(IC6/CN19/RD13) U22.3(~{FAULT})
RF6_RS232_NINVALID: U1.55(SCK1/INT0/RF6) U9.2(\~{INVALI}D)
RF12: U1.40(~{U2CTS}/RF12) U10.2(~{RE})
RF13: U1.39(~{U2RTS}/RF13) U10.3(DE)
RG12_EMFLT_A: R83.2 U1.96(RG12) U24.1(OUTA)
RG13_EMFLT_B: R85.2 U1.97(RG13) U24.6(OUTB)
RG14_EMFLT_C: R77.2 U1.95(RG14) U23.3(~{FAULT})
RG15_EMFLT_EN: R80.1 U1.1(RG15) U23.4(IN)
RS232_CTS: J5.4 U9.20(R2IN)
RS232_RTS: J5.2 U9.19(T2OUT)
RS232_RXD: J5.3 U9.8(R1IN)
RS232_TXD: J5.1 U9.7(T1OUT)
RS485_A: J4.2 U10.6(A)
RS485_B: J4.1 U10.7(B)
SOSCI: C5.1 U1.73(PGED2/SOSCI/CN1/RC13) Y1.2
SOSCO: C4.1 U1.74(PGEC2/SOSCO/T1CK/CN0/RC14) Y1.1
U1CTS: U1.47(IC7/~{U1CTS}/CN20/RD14) U9.1(R2OUT)
U1RTS: U1.48(IC8/~{U1RTS}/CN21/RD15) U9.3(T2IN)
U1RXD: U1.52(U1RX/RF2) U9.6(R1OUT)
U1TXD: U1.51(U1TX/RF3) U9.4(T1IN)
U2RXD: U1.49(U2RX/CN17/RF4) U10.1(RO)
U2TXD: U1.50(U2TX/CN18/RF5) U10.4(DI)
VOFF: U13.1(REF) U15.1(REF) U17.1(REF) U19.1(Vbias)
N08765: C1.1 C2.1 R1.2 R2.2
N08773: R2.1 U1.85(VCAP)
N14987: JP1.1 R3.2 R4.1 SW1.3 SW1.4
N25385: F5.1 J11.1
N30214: C88.1 DN3.3(J) R63.2 R64.1
N30237: C87.1 DN4.3(J) R66.2 R67.1
N30262: C89.1 DN5.3(J) R69.2 R70.1
N38405: C3.1 JP1.2
N39747: U1.29(VREF+/RA10) U2.5(Vref)
N47726: J3.1 R24.2
N61961: C48.2 C50.1 R30.2 R31.1 U13.2(IN-)
N61969: C50.2 C53.1 R31.2 R36.2 U13.3(IN+)
N62625: C57.2 C59.1 R37.2 R38.1 U15.2(IN-)
N62633: C59.2 C62.1 R38.2 R43.2 U15.3(IN+)
N63303: C66.2 C68.1 R44.2 R45.1 U17.2(IN-)
N63311: C68.2 C71.1 R45.2 R50.2 U17.3(IN+)
N72482: C77.1 DN9.3(J) R55.2 U20.5(INB+)
N72600: R51.2 R52.1 R53.2
N72690: C76.1 DN10.3(J) R52.2 U20.3(INA+)
N72804: R54.2 R55.1 R56.2
N72852: F2.1 J8.1
N75830: F1.1 J7.1
N76571: F3.1 J9.1
N76619: J9.2 R57.2 R58.1
N76675: J9.3 R58.2 R59.1
N76787: C78.1 DN1.3(J) R57.1 U21.3(INA+)
N77226: F4.1 J10.1
N77274: J10.2 R60.2 R62.1
N77330: J10.3 R61.1 R62.2
N77442: C79.1 DN2.3(J) R60.1 U21.5(INB+)
N78880: C45.2 R28.1 U12.1(OutA) U12.2(INA-)
N79170: RN1.7 RN1.8 U11.3(IN+)
N79174: RN1.5 RN1.6 U11.4(IN-)
N79202: R26.1 RN1.3 U11.1(OUT)
N79426: C45.1 R26.2 R27.1
N79442: C43.1 R27.2 U12.3(INA+)
N79600: C46.1 R28.2 R29.1
N79616: C44.1 R29.2 U12.5(INB+)
N83438: C54.2 R34.1 U14.1(OutA) U14.2(INA-)
N83538: C54.1 R32.2 R33.1
N83554: C51.1 R33.2 U14.3(INA+)
N83666: C55.1 R34.2 R35.1
N83682: C52.1 R35.2 U14.5(INB+)
N84265: C63.2 R41.1 U16.1(OutA) U16.2(INA-)
N84365: C63.1 R39.2 R40.1
N84381: C60.1 R40.2 U16.3(INA+)
N84493: C64.1 R41.2 R42.1
N84509: C61.1 R42.2 U16.5(INB+)
N85113: C72.2 R48.1 U18.1(OutA) U18.2(INA-)
N85213: C72.1 R46.2 R47.1
N85229: C69.1 R47.2 U18.3(INA+)
N85341: C73.1 R48.2 R49.1
N85357: C70.1 R49.2 U18.5(INB+)
N98820: Q1.1(G) U22.5(GATE)
N98894: Q1.3(D) R73.2 U22.6(SENSE)
N99153: C83.1 R74.2 U22.2(TIMER)
N109964: C17.1 C27.1 C28.1 JR2.1 U3.13(INTVCC) U5.6(~{Clr}) U5.7(~{Pre}) U5.8(Vcc) U6.6(V+)
N110102: C16.1 R8.1 R9.1 U3.16(FB)
N110130: C16.2 C21.1 C22.1 C23.1 L1.2 R8.2 R12.1 U3.14(BIAS) U4.7(VIN1) U4.8(VIN2)
N110228: R7.2 R10.1 U4.3(SNS)
N110370: C18.2 L1.1 U3.9(SW1) U3.10(SW2) U3.11(SW3)
N110394: C18.1 U3.12(BST)
N110516: R11.1 U3.3(RT)
N110530: C19.1 U3.2(TR/SS)
N110898: C26.1 U4.4(SS)
N110954: C25.1 R12.2 U3.15(PG) U4.5(EN)
N111056: R13.2 R15.1 U3.4(EN/UV)
N111200: U5.1(Clk) U6.1(OUT1)
N111222: R16.1 U6.4(SET)
N111288: JR2.2 U6.3(DIV)
N113208: R21.2 R23.1 U7.4(EN/UV)
N113286: D2.C R22.1
N113430: C29.1 R17.1 R18.1 U7.16(FB)
N113814: C31.2 L2.1 U7.9(SW1) U7.10(SW2) U7.11(SW3)
N113838: C31.1 U7.12(BST)
N113850: C30.1 U7.13(INTVCC)
N113978: R19.1 U7.3(RT)
N113992: C32.1 U7.2(TR/SS)
N133871: D1.C R14.1
N137397: JR4.2 U8.8(RS)
N140550: F6.2 Q2.2(S) Q3.1(G) R82.1
N140644: R86.2 R87.1 U24.4(-INB)
N140824: R84.2 R86.1 U24.3(+INA)
N140988: Q2.1(G) U23.5(GATE)
N141012: Q2.3(D) R78.2 U23.6(SENSE)
N141056: C86.1 R80.2 U23.2(TIMER)
N141914: Q3.2(S) R84.1
N143860: F6.1 R81.1
N249678: J10.4 J10.5 R89.1

Not connected (* = marked no-connect by the designer): J2 4*; J3 6*; J4 4*; J5 6*; U1 5(PWM4H/RE7)* 10(SCK2/CN8/RG6)* 11(SDI2/CN9/RG7)* 12(SDO2/CN10/RG8)* 14(~{SS2}/CN11/RG9)* 17(TMS/RA0)* 18(AN20/~{FLTA}/INT1/RE8)* 19(AN21/~{FLTB}/INT2/RE9)* 23(AN2/~{SS1}/CN4/RB2)* 32(AN8/RB8)* 33(AN9/RB9)* 38(TCK/RA1)* 41(AN12/RB12)* 42(AN13/RB13)* 43(AN14/RB14)* 44(AN15/OCFB/CN12/RB15)* 53(SDO1/RF8)* 54(SDI1/RF7)* 56(SDA1/RG3)* 57(SCL1/RG2)* 58(SCL2/RA2)* 59(SDA2/RA3)* 60(TDI/RA4)* 61(TDO/RA5)* 66(INT3/RA14)* 67(INT4/RA15)* 68(IC1/RD8)* 69(IC2/RD9)* 70(IC3/RD10)* 71(IC4/RD11)* 84(OC8/UPDN/CN16/RD7)* 89(C2TX/RG1)* 90(C2RX/RG0)* 91(AN22/CN22/RA6)* 92(AN23/CN23/RA7)*; U2 1(Vbias)*; U3 7(NC)*; U6 5(GRD); U7 7(NC)*; U9 11(V+_1)* 12(V+_2)* 13(C1+)* 14(C1-)* 15(C2+)* 16(C2-)* 17(V-)*; U13 5(GAIN2)* 8(GAIN1)*; U15 5(GAIN2)* 8(GAIN1)*; U17 5(GAIN2)* 8(GAIN1)*; U19 5(Vref)*; U22 7(NC)*; U23 7(NC)*

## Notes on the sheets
sheet 1
- DNI
- COMPONENTS IN THIS NETWORK
  TO BE PLACED WITHIN 0.25" OF
  MCLR PIN
- RESET BUTTON
- REMOVE JUMPER
  FOR PROGRAMMING
- SECONDARY OSC
- ATTEMPT GUARD TRACES
  SEE DSPIC REFERENCE MANUAL
- DNI
- PRECISION VOLTAGE REFERENCE
- PRIMARY OSC
- PLACE 0.1uF NEAR
  NUMBERED TERMINALS
  SAME SIDE AS IC
- 2
- 16
- 30
- 37
- 46
- 62
- 86
- 29
- 15
- 31
- 38
- 45
- 65
- 75
- 29
sheet 2
- 3.3V STEPDOWN
- CCM
- DNI
- Vfb = 0.97V
- Burst
- INPUT POWER
- Primary Step Down Voltage = 3.45V
- Undervoltage and
  Enable at 1.0V (10VIN)
- Power Good Signal holds final until
  nearly charged
- 200kHz
- Caution - INTVcc not really supposed to be used!
- 200kHz
- 400kHz
- Guard Trace wraps around  trace of pin 4
- H = DIV 10
  None = DIV 3
  L = DIV 1
- JR2 = L
- 5V STEPDOWN
- CCM
- DNI
- Burst
- Primary Step Down Voltage = 5.00V
- Vfb = 0.97V
- Final System voltage = 5.0V
- Undervoltage and
  Enable at 1.0V (10VIN)
- Power Good Signal holds final until
  nearly charged
sheet 3
- MODE SELECT
  H = LOW POWER (10K)
  L = HIGH SPEED (0K)
  L = SLOPE CONTROL (10K-100K)
  DEFAULT HIGH SPEED
- CANBUS
- MPLAB ICD CONNECTOR
- STEPPER MOTOR RS485
- RS232
sheet 4
- GEN HOUSING CONFIG:
  OMEGA DIFF PRESSURE / TORQUE SENSOR
  OUTPUT 0-10VDC SUPPLY 15VDC
  DO NOT DIRECTLY ATTACH TORQUE SENSOR USE REDLION
- GAS SPRING CONFIG:
  HONEYWELL PRESSURE SENSOR A
  0-10VDC 4WIRE 15VDC SUPPLY
- 100Hz LPF
- APPROXIMATE OUTPUT
  0-3.1 V
  0.8 mV / ADC COUNT @ 12-BIT
- 100Hz LPF
- GAS SPRING CONFIG:
  HONEYWELL PRESSURE SENSOR B
  0-10VDC 4WIRE 15VDC SUPPLY
- 100Hz LPF
- APPROXIMATE OUTPUT
  0-3.1 V
  0.8 mV / ADC COUNT @ 12-BIT
- 100Hz LPF
- GAS SPRING CONFIG:
  LOAD CELL ICA5
  OUTPUT 4-20mA 2-WIRE
  SUPPLY 7.5-28VDC
  LOOP ON PINS 1 & 2
- APPROXIMATE OUTPUT
  0.64 V  = 0 LBS
  3.20 V  = 10,000 LBS
  3.15 LBS / ADC COUNT @ 12-BIT
  OFFSET = 794 COUNTS
- 100Hz LPF
- FROM LOAD CELL
  4mA  =            0 LBS
  20mA = 10000 LBS
  MAX SHUNT RES 365 OHM @ 15VIN
- GAS SPRING CONFIG:
  LASER RANGE FINDER MRL-ML1
  OUTPUT 0-20mA 4-WIRE
  SUPPLY 15-24VDC
- APPROXIMATE OUTPUT
  0 V  = 0 m
  3.20 V  = 2400 mm
   0.6 mm / ADC COUNT @ 12-BIT
- 100Hz LPF
- DO NOT LOAD
- DO NOT LOAD
- FROM LASER RANGE FINDER
  (PRECONFIGURED MAX 2.4m)
  0 mA  =    0 m
  20mA = 2.4 m
sheet 5
- DIODES SCHOTTKY SOT 323
- MOTOR DIGITAL OUTPUTS
- MAX 120kHz
- MOTOR DIGITAL INPUTS
- NO FILTER INSTALLED
- MAX 120kHz
- LASER RANGEFINDER POWER SWITCHING
- DNI
- MAX 120kHz
- Current Limiting Resistor:
  Rs = 50mV/Iset
  Iset =     1A
- INAPPROPRIATE LPF R VALUES
  CHANGE TO 330 OHM
- MAX 1kHz
- Approximate self reset
  700ms without resistor.
- MAX 1kHz
- EM CABLE FAULT DETECTOR
- Current Limiting Resistor:
  Rs = 50mV/Iset
  Iset =     1mA
- TEST MAX 700uA
- MAX 1kHz
- Approximate self reset
  700ms without resistor.
- GAS BYPASS VALVE DO
- STEPPER ENABLE DO
- TRUTH TABLE
- A  B  C
  0  1  0
  1  0  1
  1  1  1
  0  1  1
- OVERCURRENT = SHORTED
  RWIRE < 30KOHM
  30KOHM < RWIRE < 51KOHM
  RWIRE > 50KOHM**
- **OR TOTALLY OPEN
sheet 6
- ACASA1002E1502P100:
  R1=R4=10K
  R2=R3=15K
- FILTER CUTOFF 2kHz, -72dB @ 16kHz
- BUS VOLTAGE = 0 to 400V
  VOUT = 0 to 3V pre-filter
- GEN HOUSING CONFIG:
  VOLTAGE/CURRENT SHUNT MONITOR INPUTS
  DIFFERENTIAL 0-5V
- FILTER CUTOFF 2kHz, -72dB @ 16kHz
- FILTER CUTOFF 2kHz, -72dB @ 16kHz
- FILTER CUTOFF 2kHz, -72dB @ 16kHz
- OFFSET VOLTAGE FOR DIFFERENTIAL
  TO SINGLE ENDED CONVERSION
